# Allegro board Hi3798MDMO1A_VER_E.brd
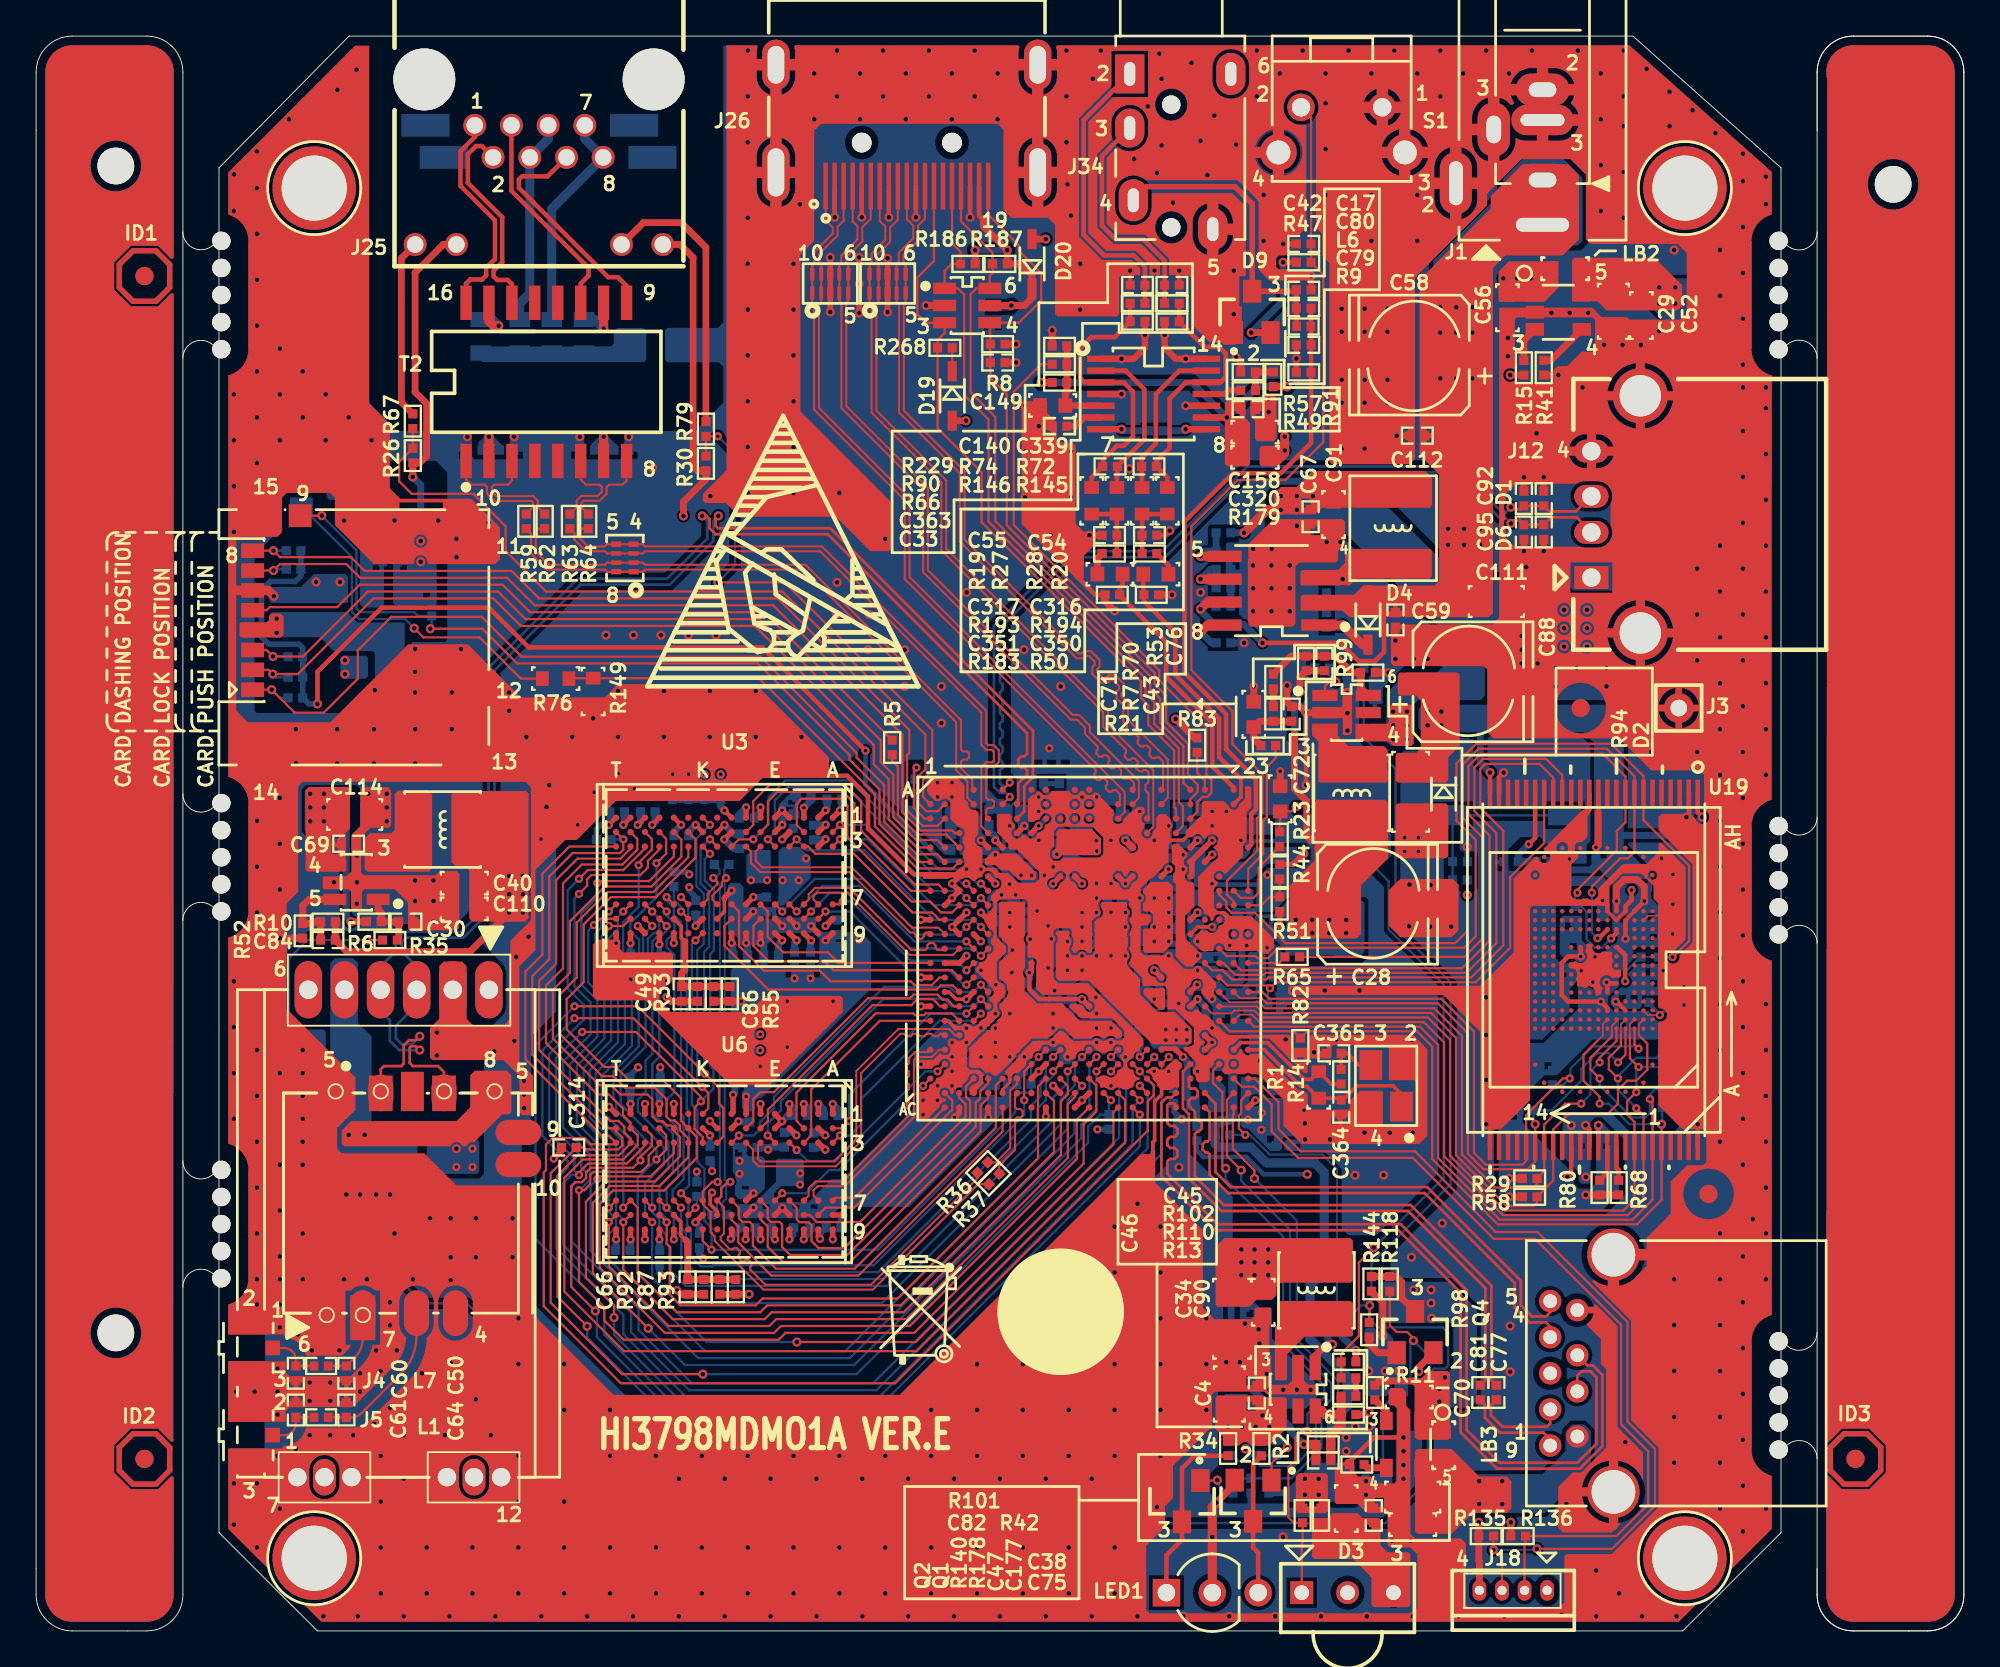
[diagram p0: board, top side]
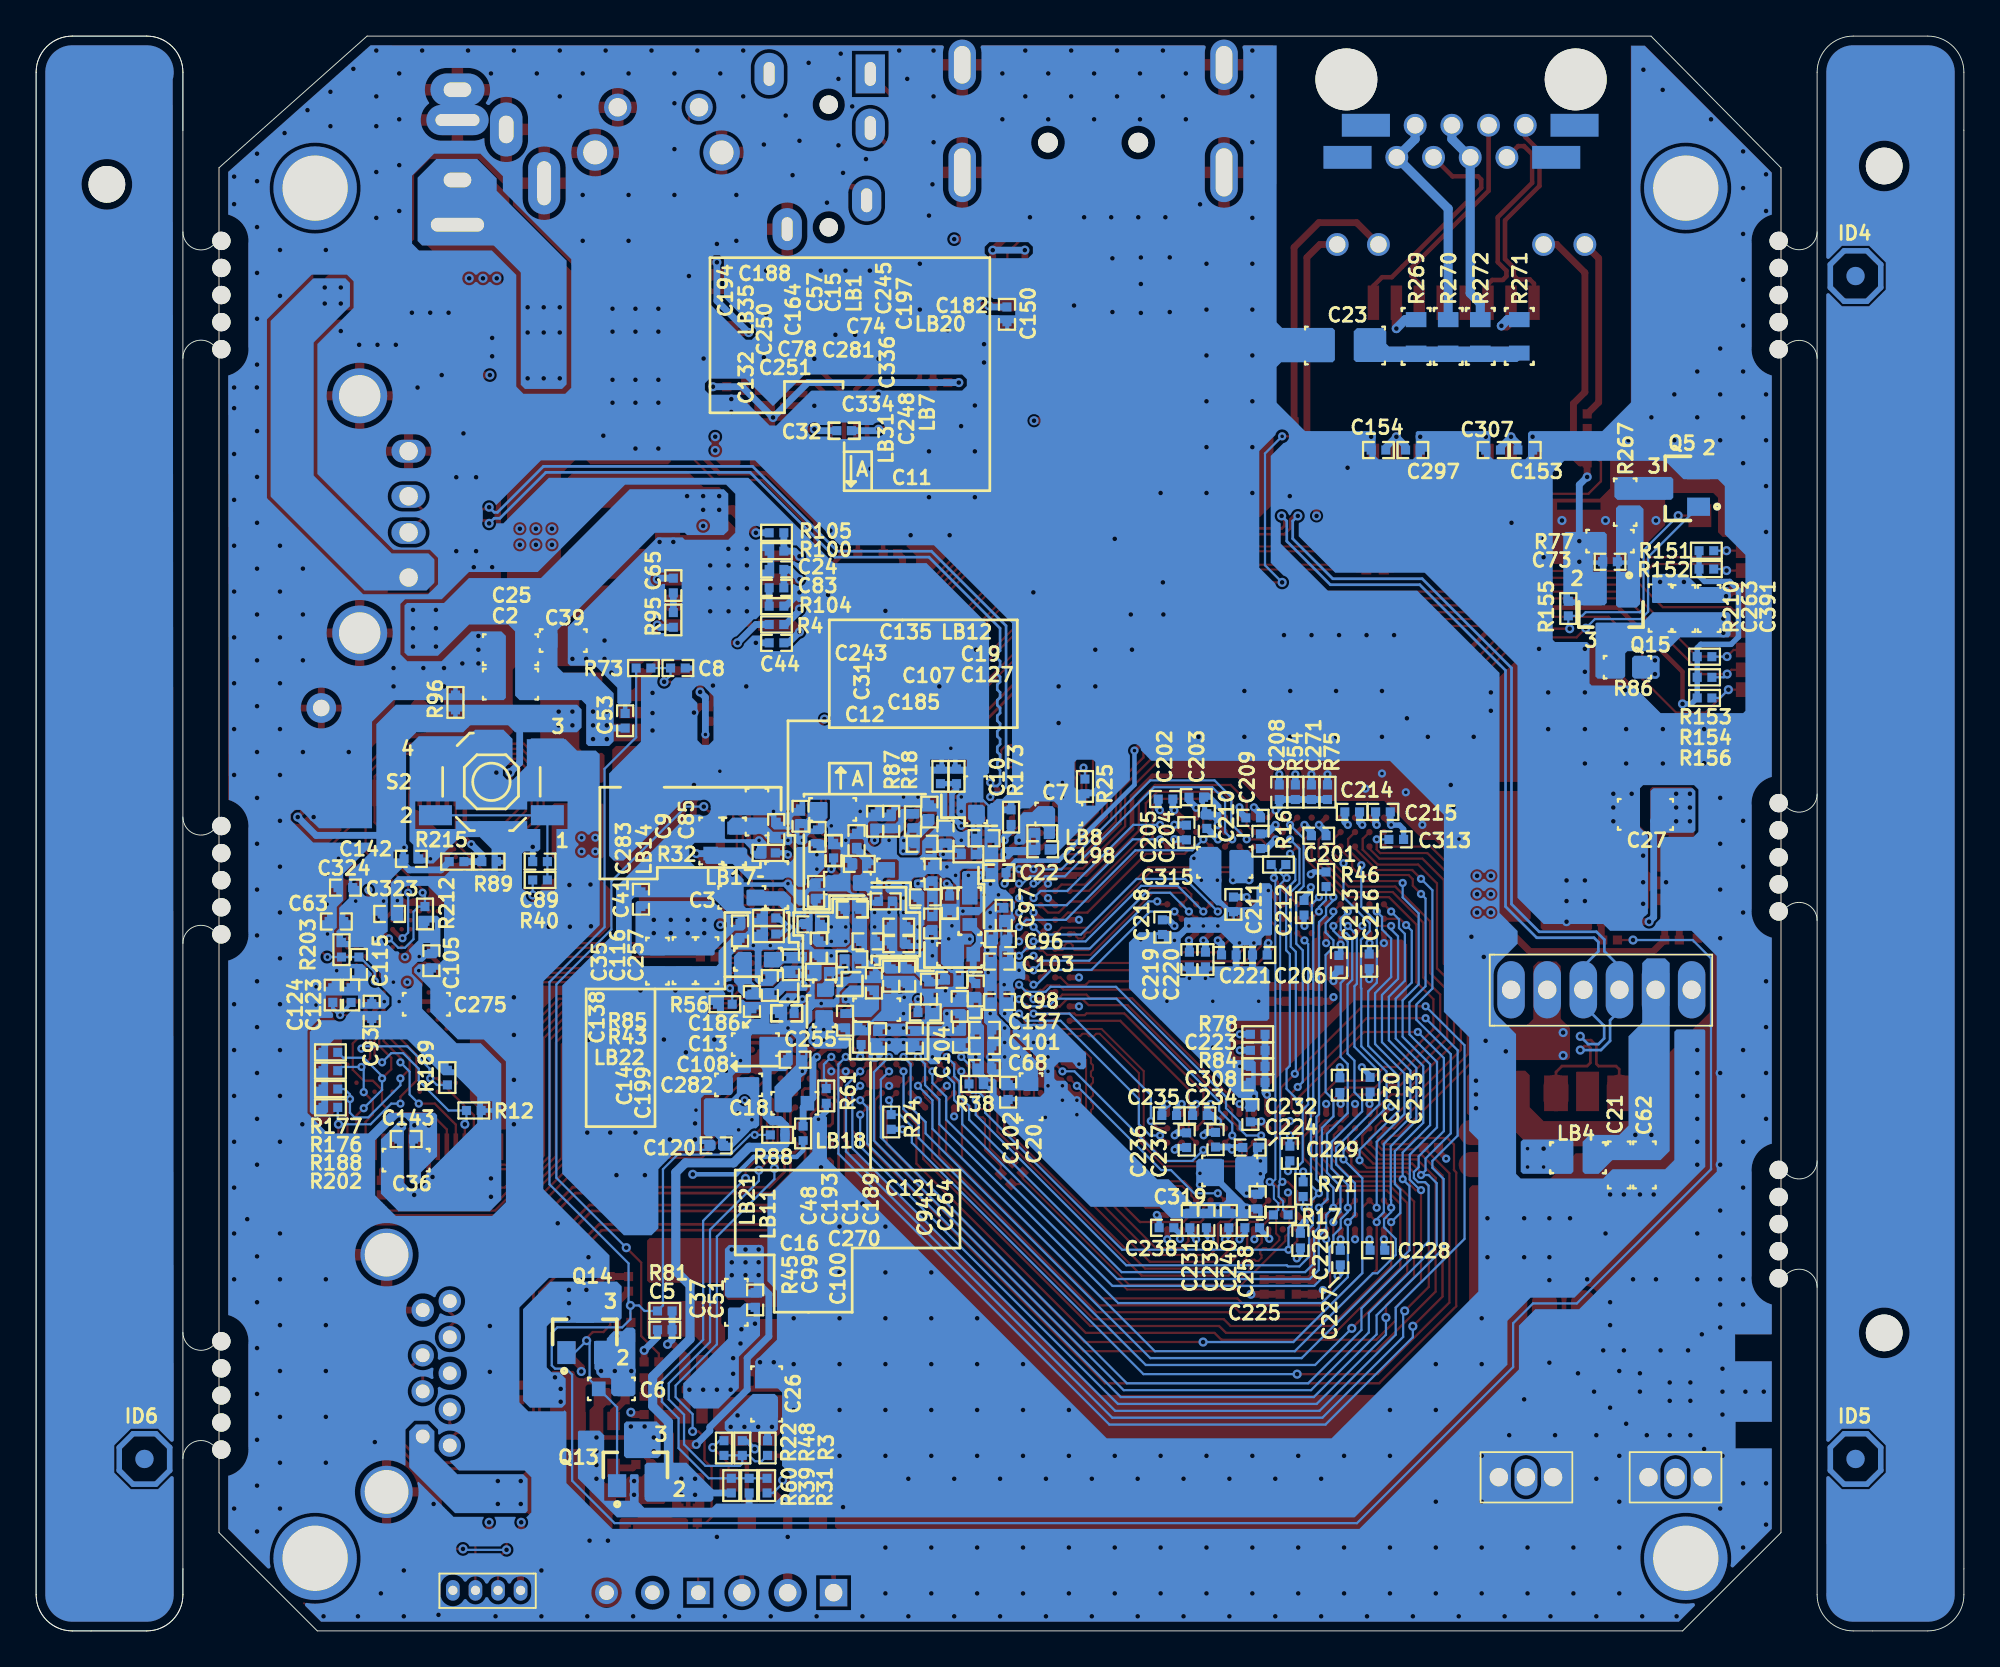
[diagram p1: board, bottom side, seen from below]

Outline 106.76 x 88.35 mm; copper layers: TOP, GND02, POWER03, BOTTOM. Coordinates in mm from the lower left corner of the outline.
Outline path: 98.63,86.35 98.63,83.14 ; 98.63,86.35 arc(99.21,87.76) 100.63,88.35 ; 98.63,86.35 arc(99.21,87.76) 100.63,88.35 ; 98.63,86.35 98.63,83.14 ; 98.63,83.14 98.63,3.43 ; 100.63,88.35 104.76,88.35 ; 100.63,88.35 104.76,88.35 ; 98.63,3.43 98.63,2 ; 98.63,3.43 98.63,2 ; 98.63,2 arc(99.21,0.59) 100.63,0 ; 98.63,2 arc(99.21,0.59) 100.63,0 ; 104.76,88.35 arc(106.17,87.76) 106.76,86.35 ; 104.76,88.35 arc(106.17,87.76) 106.76,86.35 ; 100.63,0 103.71,0 ; 100.63,0 103.71,0 ; 103.71,0 104.76,0 ; 103.71,0 104.76,0 ; 104.76,0 arc(106.17,0.59) 106.76,2 ; 104.76,0 arc(106.17,0.59) 106.76,2 ; 106.76,86.35 106.76,2 ; 106.76,86.35 106.76,2 ; 0,86.35 0,2 arc(0.59,0.59) 2,0 6.13,0 arc(7.54,0.59) 8.13,2 8.13,86.35 arc(7.54,87.76) 6.13,88.35 2,88.35 arc(0.59,87.76) 0,86.35 ; 10.13,81.05 17.33,88.35 88.43,88.35 96.63,81.05 96.63,5.44 91.18,0 15.57,0 10.13,5.45 10.13,81.05

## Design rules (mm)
constraint set DEFAULT: min track width 0.127
net group $5N541: nets 5V0 $5N541
net group $5N549: nets $5N549 STANDBY_PWROFF
net group $7N1630: nets $7N1630 USB_BOOT
net group $8N1514: nets $8N1514 DDR_CLK1P
net group $8N1515: nets $8N1515 DDR_CLK1N
net group $14N708: nets $14N708 USB3_TXN
net group $14N709: nets $14N709 USB3_TXP
net group $17N167: nets $17N167 TX+_PHY0
net group $17N169: nets $17N169 TX-_PHY0
net group DIFF: nets RX+_PHY0 RX-_PHY0
net group DIFFPAIR8: nets DDR_DQS0N DDR_DQS0P
net group DIFFPAIR9: nets DDR_DQS1N DDR_DQS1P
net group DIFFPAIR10: nets DDR_DQS2N DDR_DQS2P
net group DIFFPAIR11: nets DDR_DQS3N DDR_DQS3P
net group DIFFPAIR21: nets $17N178 $17N179
net group DIFFPAIR22: nets $17N175 $17N176
net group DIFFPAIR23: nets USB3_RXN USB3_RXP
net group USB: nets USB3_DM USB3_DP
net group 00: nets GND
net group 01: nets ADAC_VOUTL ADAC_VOUTR MUTE_CTRL
net group 02: nets 1V1_CPU
net group $17N168: nets $17N168
net group $17N182: nets $17N182
net group DDR: nets DDR_ADDR0 DDR_ADDR1 DDR_ADDR2 DDR_ADDR3 DDR_ADDR4 DDR_ADDR5 DDR_ADDR6 DDR_ADDR7 DDR_ADDR8 DDR_ADDR9 DDR_ADDR10 DDR_ADDR11 DDR_ADDR12 DDR_ADDR13 DDR_ADDR14 DDR_ADDR15 DDR_BA0 DDR_BA1 DDR_BA2 DDR_CASN DDR_CKE DDR_CSN DDR_DM0 DDR_DM1 DDR_DM2 DDR_DM3 DDR_DQ0 DDR_DQ1 DDR_DQ2 DDR_DQ3 DDR_DQ4 DDR_DQ5 DDR_DQ6 DDR_DQ7 DDR_DQ8 DDR_DQ9 DDR_DQ10 DDR_DQ11 DDR_DQ12 DDR_DQ13 DDR_DQ14 DDR_DQ15 DDR_DQ16 DDR_DQ17 DDR_DQ18 DDR_DQ19 DDR_DQ20 DDR_DQ21 DDR_DQ22 DDR_DQ23 DDR_DQ24 DDR_DQ25 DDR_DQ26 DDR_DQ27 DDR_DQ28 DDR_DQ29 DDR_DQ30 DDR_DQ31 DDR_ODT DDR_RASN DDR_RESETN DDR_WEN
net group DIFF90: nets USB0_DM USB0_DP USB1_DM USB1_DP
net group POWER: nets 1V1_CORE 1V5_DDR3 3V3_MOS
net group VIN: nets 3V3

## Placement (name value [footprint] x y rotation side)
C1  1NF  [SC0402]  58.52 36.27 270 bottom
C2  22UF  [SC0805]  80.49 52.45 0 bottom
C3  220NF  [SC0603]  67.67 40.64 0 bottom
C4  22UF  [SC0805]  66.07 13.13 90 top
C5  1NF  [SC0402]  71.94 16.68 0 bottom
C6  220NF  [SC0603]  74.9 13.41 0 bottom
C7  220NF  [SC0603]  50.12 45.26 180 bottom
C8  1NF  [SC0402]  71.21 53.34 180 bottom
C9  220NF  [SC0603]  66.84 45.36 90 bottom
C10  220NF  [SC0603]  54.72 46.05 90 bottom
C11  220NF  [SC0603]  55.56 37.49 0 bottom
C12  1NF  [SC0402]  63.28 36.51 0 bottom
C13  220NF  [SC0603]  66.92 32.48 0 bottom
C14  1NF  [SC0402]  66.12 35.76 90 bottom
C15  1NF  [SC0402]  59.41 44.85 90 bottom
C16  220NF  [SC0603]  60.21 34.41 180 bottom
C17  1NF  [SC0402]  70.2 74.3 0 top
C18  220NF  [SC0603]  64.74 29.23 0 bottom
C19  1NF  [SC0402]  58.99 39.01 180 bottom
C20  220NF  [SC0603]  51.66 29.59 270 bottom
C21  220NF  [SC0603]  19.09 25.81 270 bottom
C22  330N  [HSC0402]  53.45 42.01 180 bottom
C23  1NF  [SC1206]  34.27 71.21 0 bottom
C24  1NF  [SC0402]  65.75 58.8 0 bottom
C25  22UF  [SC0805]  80.49 54.36 0 bottom
C26  22UF  [SC0805]  66.3 13.13 90 bottom
C27  22UF  [SC0805]  17.64 45.23 0 bottom
C28  100UF  [SAC6666]  74.29 40.25 0 top
C29  22UF  [SC0805]  87.34 73.1 270 top
C30  1NF  [SC0402]  20.48 39.29 0 top
C31  330N  [HSC0402]  63.41 37.82 270 bottom
C32  330N  [HSC0402]  62.01 66.49 0 bottom
C33  330N  [HSC0402]  56.68 66.74 0 top
C34  1NF  [SC1206]  66.23 17.29 270 top
C35  220NF  [SC0603]  72.35 37.1 270 bottom
C36  220NF  [SC0603]  86.27 26.08 180 bottom
C37  220NF  [SC0603]  67.98 18.21 270 bottom
C38  22UF  [SC0805]  76.23 7.41 180 top
C39  220NF  [SC0603]  77.56 54.86 180 bottom
C40  220NF  [SC0603]  23.71 41.42 180 top
C41  1NF  [SC0402]  73.26 40.53 90 bottom
C42  1NF  [SC0402]  70.2 76.83 0 top
C43  1NF  [SC0402]  69.53 50.8 90 top
C44  1NF  [SC0402]  65.75 54.74 0 bottom
C45  1NF  [SC0402]  72.68 14.91 0 top
C46  1NF  [SC0402]  67.6 13.18 90 top
C47  220NF  [SC0603]  72.55 6.78 90 top
C48  1NF  [SC0402]  60.36 35.89 90 bottom
C49  1NF  [SC0402]  35.75 35.29 90 top
C50  1NF  [SC0402]  17.18 14.27 270 top
C51  1NF  [SC0402]  66.94 18.33 270 bottom
C52  220NF  [SC0603]  88.89 72.87 270 top
C53  1NF  [SC0402]  74.14 50.42 90 bottom
C54  1NF  [SC0402]  61.63 64.51 180 top
C55  1NF  [SC0402]  59.47 64.51 180 top
C56  220NF  [SC0603]  81.48 73.3 270 top
C57  1NF  [SC0402]  60.29 44.85 90 bottom
C58  100UF  [SAC6666]  76.05 70.68 180 top
C59  1NF  [SC0402]  75.28 56.01 270 top
C60  1NF  [SC0402]  14.39 14.27 270 top
C61  1NF  [SC0402]  14.39 12.24 90 top
C62  220NF  [SC0603]  17.69 25.81 270 bottom
C63  1NF  [SC0402]  90.13 39.3 0 bottom
C64  1NF  [SC0402]  17.18 12.24 90 top
C65  1NF  [SC0402]  71.47 57.91 90 bottom
C66  1NF  [SC0402]  36.08 19.06 90 top
C67  1NF  [SC0402]  70.58 61.72 270 top
C68  1NF  [SC0402]  54.24 31.19 0 bottom
C69  1NF  [SC0402]  17.31 43.61 0 top
C70  220NF  [SC0603]  76.04 12.95 180 top
C71  220NF  [SC0603]  67.43 50.77 90 top
C72  220NF  [SC0603]  68.89 46.1 90 top
C73  1NF  [SC0402]  19.6 59.23 180 bottom
C74  1NF  [SC0402]  57.69 43.61 180 bottom
C75  220NF  [SC0603]  76.23 5.89 180 top
C76  1NF  [SC0402]  71.34 53.59 270 top
C77  1NF  [SC0402]  80.87 13.21 90 top
C78  1NF  [SC0402]  61.17 42.49 0 bottom
C79  1NF  [SC0402]  70.2 71.25 180 top
C80  1NF  [SC0402]  70.2 73.28 180 top
C81  1NF  [SC0402]  79.98 13.21 90 top
C82  1NF  [SC0402]  71.28 9.44 180 top
C83  1NF  [SC0402]  65.75 57.78 0 bottom
C84  1NF  [SC0402]  16.16 38.27 0 top
C85  1NF  [SC0402]  65.77 44.39 90 bottom
C86  1NF  [SC0402]  37.53 35.29 270 top
C87  1NF  [SC0402]  37.86 19.06 270 top
C88  100UF  [SAC6666]  79.57 52.58 0 top
C89  1NF  [SC0402]  78.85 42.62 0 bottom
C90  220NF  [SC0603]  67.95 18.21 270 top
C91  220NF  [SC0603]  71.85 61.85 270 top
C92  1NF  [SC0402]  82.39 62.73 90 top
C93  1NF  [SC0402]  88.17 34.34 90 bottom
C94  1NF  [SC0402]  55.61 34.59 90 bottom
C95  1NF  [SC0402]  82.39 60.88 270 top
C96  1NF  [SC0402]  53.35 38.32 180 bottom
C97  1NF  [SC0402]  53.17 39.64 270 bottom
C98  1NF  [SC0402]  53.4 34.84 180 bottom
C99  1NF  [SC0402]  60.13 32.81 270 bottom
C100  1NF  [SC0402]  58.1 32.84 270 bottom
C101  1NF  [SC0402]  54.24 32.41 0 bottom
C102  1NF  [SC0402]  52.93 29.84 270 bottom
C103  1NF  [SC0402]  53.4 37.08 180 bottom
C104  1NF  [SC0402]  55.53 32.89 270 bottom
C105  1NF  [SC0402]  84.87 37.13 270 bottom
C107  1NF  [SC0402]  60.69 38.2 0 bottom
C108  1NF  [SC0402]  64.73 31.64 180 bottom
C110  220NF  [SC0603]  23.71 40 180 top
C111  22UF  [SC0805]  80.87 57.02 0 top
C112  1NF  [SC0402]  76.49 66.21 180 top
C114  22UF  [SC0805]  17.64 45.23 0 top
C115  1NF  [SC0402]  88.88 36.92 270 bottom
C116  220NF  [SC0603]  70.87 37.13 270 bottom
C120  1NF  [SC0402]  69.1 26.89 0 bottom
C121  1NF  [SC0402]  56.04 36.06 180 bottom
C123  1NF  [SC0402]  89.31 35.22 90 bottom
C124  1NF  [SC0402]  90.33 35.22 90 bottom
C127  1NF  [SC0402]  58.99 38.04 180 bottom
C132  1NF  [SC0402]  63.56 40.97 90 bottom
C135  330N  [HSC0402]  61.55 39.98 180 bottom
C137  1NF  [SC0402]  54.24 33.29 0 bottom
C138  1NF  [SC0402]  67.78 38.78 270 bottom
C140  1NF  [SC0402]  60.99 74.56 180 top
C142  1NF  [SC0402]  85.98 42.77 180 bottom
C143  1NF  [SC0402]  86.26 27.25 180 bottom
C149  1NF  [SC0402]  53.25 70.27 0 top
C150  1NF  [SC0402]  52.99 72.93 270 bottom
C153  1NF  [SC0402]  24.29 65.42 180 bottom
C154  1NF  [SC0402]  32.42 65.42 0 bottom
C158  1NF  [SC0402]  67.12 67.68 0 top
C164  1NF  [SC0402]  61.32 43.79 90 bottom
C177  1NF  [SC0402]  74.08 6.4 90 top
C182  1NF  [SC0402]  54.26 43.91 180 bottom
C185  1NF  [SC0402]  61.58 37.21 180 bottom
C186  1NF  [SC0402]  67.12 34.87 270 bottom
C188  220NF  [SC0603]  62.65 45.51 180 bottom
C189  1NF  [SC0402]  57.31 35.56 270 bottom
C193  1NF  [SC0402]  59.41 36.27 270 bottom
C194  1NF  [SC0402]  64.42 45.13 90 bottom
C197  1NF  [SC0402]  56.4 44.04 90 bottom
C198  1NF  [SC0402]  51.01 43.3 180 bottom
C199  1NF  [SC0402]  64.96 36.9 270 bottom
C201  1NF  [SC0402]  35.73 44.05 180 bottom
C202  1NF  [SC0402]  44.21 46.08 180 bottom
C203  1NF  [SC0402]  42.51 46.18 180 bottom
C204  1NF  [SC0402]  41.92 44.86 90 bottom
C205  1NF  [SC0402]  43.06 44.23 270 bottom
C206  1NF  [SC0402]  38.99 37.44 0 bottom
C208  1NF  [SC0402]  37.91 46.46 270 bottom
C209  1NF  [SC0402]  39.36 45.04 180 bottom
C210  1NF  [SC0402]  38.95 43.75 90 bottom
C211  1NF  [SC0402]  40.45 40.25 270 bottom
C212  1NF  [SC0402]  36.54 40.06 90 bottom
C213  1NF  [SC0402]  34.61 37.01 270 bottom
C214  1NF  [SC0402]  33.87 45.37 180 bottom
C215  1NF  [SC0402]  32.17 45.37 180 bottom
C216  1NF  [SC0402]  32.93 37.09 270 bottom
C218  1NF  [SC0402]  44.39 38.98 270 bottom
C219  1NF  [SC0402]  42.89 37.19 270 bottom
C220  1NF  [SC0402]  42 37.19 270 bottom
C221  1NF  [SC0402]  40.71 37.45 180 bottom
C223  1NF  [SC0402]  39.11 32.16 180 bottom
C224  1NF  [SC0402]  39.52 26.78 0 bottom
C225  1NF  [SC0402]  39.41 22.33 0 bottom
C226  1NF  [SC0402]  36.74 21.62 270 bottom
C227  1NF  [SC0402]  34.53 20.68 270 bottom
C228  1NF  [SC0402]  32.48 21.09 180 bottom
C229  1NF  [SC0402]  37.33 26.45 270 bottom
C230  1NF  [SC0402]  34.56 30.23 90 bottom
C231  1NF  [SC0402]  42.86 22.74 90 bottom
C232  1NF  [SC0402]  39.51 28.61 90 bottom
C233  1NF  [SC0402]  32.88 30.26 90 bottom
C234  1NF  [SC0402]  42.31 28.56 180 bottom
C235  1NF  [SC0402]  44.01 28.56 180 bottom
C236  1NF  [SC0402]  43.04 27.18 270 bottom
C237  1NF  [SC0402]  41.44 27.21 270 bottom
C238  1NF  [SC0402]  44.16 22.33 180 bottom
C239  1NF  [SC0402]  41.95 22.74 90 bottom
C240  1NF  [SC0402]  40.71 22.74 90 bottom
C243  1NF  [SC0402]  63.74 39.14 0 bottom
C245  1NF  [SC0402]  57.29 45.36 90 bottom
C248  330N  [HSC0402]  56.17 40.31 270 bottom
C250  330N  [HSC0402]  62.59 43.23 270 bottom
C251  220NF  [SC0603]  61.83 41.42 0 bottom
C255  330N  [HSC0402]  65.19 34.21 180 bottom
C257  220NF  [SC0603]  69.6 37.13 270 bottom
C258  1NF  [SC0402]  39.11 23.78 270 bottom
C263  220NF  [SC0603]  15.5 56.64 90 bottom
C264  1NF  [SC0402]  54.72 35.45 270 bottom
C270  1NF  [SC0402]  57.51 34.26 180 bottom
C271  1NF  [SC0402]  36.13 46.46 90 bottom
C275  220NF  [SC0603]  85.15 34.71 180 bottom
C281  220NF  [SC0603]  58.89 42.16 180 bottom
C282  220NF  [SC0603]  67.85 30.25 0 bottom
C283  220NF  [SC0603]  69.4 43.76 90 bottom
C297  1NF  [SC0402]  30.51 65.42 180 bottom
C307  1NF  [SC0402]  26.07 65.42 0 bottom
C308  1NF  [SC0402]  39.11 30.39 0 bottom
C313  1NF  [SC0402]  31.43 43.85 180 bottom
C314  1NF  [SC0402]  29.5 26.78 180 top
C315  22UF  [SC0805]  40.93 42.58 0 bottom
C316  1NF  [SC0402]  61.65 60.7 0 top
C317  1NF  [SC0402]  59.44 60.7 180 top
C319  22UF  [SC0805]  40.65 25.48 0 bottom
C320  220NF  [SC0603]  67.5 66.41 0 top
C323  1NF  [SC0402]  87.18 39.72 180 bottom
C324  1NF  [SC0402]  89.63 41.18 0 bottom
C334  1NF  [SC0402]  57.51 40.64 0 bottom
C336  1NF  [SC0402]  57.11 41.93 90 bottom
C339  1NF  [SC0402]  62.9 74.56 0 top
C350  220NF  [SC0603]  62.01 58.54 180 top
C351  220NF  [SC0603]  59.47 58.54 180 top
C363  220NF  [SC0603]  56.3 67.88 180 top
C364  1NF  [SC0402]  72.28 29 270 top
C365  1NF  [SC0402]  71.87 32 180 top
C391  220NF  [SC0603]  14.11 56.64 90 bottom
D1  1NF  [SC0402]  83.49 62.73 90 top
D2  D_A  [HSOD323A]  77.95 46.35 90 top
D3  IR  [SEN3-100C]  72.63 2.12 0 top
D4  D_A  [HSOD323A]  73.75 56.01 270 top
D6  1NF  [SC0402]  83.49 60.88 270 top
D9  D2-3_A  [SOT23]  67.34 73.07 0 top
D19  D_A  [HSOD323A]  50.73 68.41 90 top
D20  D_A  [HSOD323A]  55.15 75.73 270 top
ID1  PCB_MARKPOINT_A  [ID-BOARD]  6 75.06 0 top
ID2  PCB_MARKPOINT_A  [ID-BOARD]  6 9.53 0 top
ID3  PCB_MARKPOINT_A  [ID-BOARD]  100.76 9.53 0 top
ID4  PCB_MARKPOINT_A  [ID-BOARD]  6 75.06 180 bottom
ID5  PCB_MARKPOINT_A  [ID-BOARD]  6 9.53 180 bottom
ID6  PCB_MARKPOINT_A  [ID-BOARD]  100.76 9.53 180 bottom
J1  DC_012_HW  [PWC3-RF-A]  83.42 77.9 90 top
J2  VALUE  [SIP12-2_0MM-1827]  20.07 22.02 270 top
J3  NC  [SIP-1P]  90.97 51.13 0 top
J4  51_3612_50_H  [HSCOX-AMC-TM-A]  11.75 15.68 270 top
J5  51_3612_50_H  [HSCOX-AMC-TM-A]  11.75 10.84 270 top
J10  NC  [DC-002]  83.42 80.38 0 top
J12  SMDUSBA  [USB4-1415]  86.13 58.35 90 top
J13  USB3_ATYPE  [USB3_0_9P_DIP_MAINSUPER]  85.35 10.77 90 top
J18  SDW12501_4A_HW  [WBC0104-49T]  83.68 2.24 180 top
J21  5031820832  [MICRO_SD8-PUSH]  17.6 55.04 270 top
J25  406533_1  [MJ8-RLY]  24.29 83.41 0 top
J26  0  [WBC0119-20R-A]  48.22 85.19 180 top
J34  -  [VAF6-1107]  60.56 86.25 270 top
L1  1NH  [SL0402]  15.78 11.83 0 top
L2  3.3UH  [SWPA4020S]  72.86 46.43 270 top
L3  3.3UH  [SWPA4020S]  70.9 18.87 90 top
L4  3.3UH  [SWPA4020S]  22.51 44.39 0 top
L5  6.8UH  [SWPA5040S]  75.15 61.09 90 top
L6  1NH  [SL0402]  70.2 72.26 180 top
L7  1NH  [SL0402]  15.78 14.68 0 top
LB1  1NH  [SL0402]  58.2 44.85 270 bottom
LB2  MGLB1608_030T_LF  [SL0603]  84.68 75.46 180 top
LB3  MGLB1608_030T_LF  [SL0603]  77.95 10.29 90 top
LB4  MGLB2012_220T_LF  [SL0805]  21.37 26.21 0 bottom
LB7  MGLB1608_030T_LF  [SL0603]  55.05 39.87 90 bottom
LB8  1NH  [SL0402]  51.04 44.19 0 bottom
LB11  1NH  [SL0402]  61.96 33.8 90 bottom
LB12  1NH  [SL0402]  59.71 40.41 180 bottom
LB14  MGLB1608_030T_LF  [SL0603]  68.08 43.74 90 bottom
LB17  MGLB1608_030T_LF  [SL0603]  65.74 41.32 90 bottom
LB18  1NH  [SL0402]  64.28 27.56 90 bottom
LB20  1NH  [SL0402]  55.13 43.02 180 bottom
LB21  MGLB1608_030T_LF  [SL0603]  63.1 34.76 90 bottom
LB22  MGLB1608_030T_LF  [SL0603]  66.79 37.21 0 bottom
LB31  1NH  [SL0402]  57.13 39.19 90 bottom
LB35  1NH  [SL0402]  63.48 43.99 90 bottom
LED1  209_3SYGSURC_S530_A3HW  [LED3C-100C]  62.59 2.12 0 top
M20  M3_HOLE_A  [HOLE182-142]  91.3 4.02 0 top
M21  M3_HOLE_A  [HOLE182-142]  15.4 4.02 0 top
M22  M3_HOLE_A  [HOLE182-142]  91.3 79.93 0 top
M23  M3_HOLE_A  [HOLE182-142]  15.4 79.93 0 top
NOREF  -  []  -204.22 -199.15 0 top
NOREF#2  -  [unnamed#2]  97.63 41.59 90 top
NOREF#3  -  []  104.62 88.65 0 top
NOREF#4  -  []  -0.03 22.99 0 top
NOREF#5  -  []  138.77 142.52 180 top
NOREF#6  -  [unnamed#2]  9.13 42.86 270 top
NOREF#7  -  [unnamed#3]  4.41 81.15 0 top
NOREF#8  -  [unnamed#2]  97.63 74 90 top
NOREF#9  -  []  10.13 8.64 0 top
NOREF#10  -  []  51.53 17.91 0 top
NOREF#11  -  []  57.24 17.91 0 top
NOREF#12  -  []  41.88 56.77 0 top
NOREF#13  -  [unnamed#2]  9.13 74 270 top
NOREF#14  -  []  19.53 0 90 top
NOREF#15  -  [unnamed#2]  97.63 13.04 90 top
NOREF#16  -  []  55.55 188.89 0 top
NOREF#17  -  [unnamed#3]  4.41 16.51 0 top
NOREF#18  -  [unnamed#2]  9.13 22.54 270 top
NOREF#19  -  [unnamed#3]  102.84 80.14 0 top
NOREF#20  -  []  38.72 139.19 0 top
Q1  D2-3_A  [SOT23]  67.39 7.21 180 top
Q2  D2-3_A  [SOT23]  63.46 7.18 180 top
Q4  D2-3_A  [SOT23]  76.36 16.56 0 top
Q5  D2-3_A  [SOT23]  15.84 63.29 90 bottom
Q13  D2-3_A  [SOT23]  73.57 9.19 180 bottom
Q14  D2-3_A  [SOT23]  76.37 16.56 180 bottom
Q15  D2-3_A  [SOT23]  19.54 56.31 0 bottom
R1  5.1K  [SR0603]  71.03 30.25 270 top
R2  0/NC  [SR0402]  67.85 10.1 270 top
R3  0/NC  [SR0402]  66.25 10.13 270 bottom
R4  0/NC  [SR0402]  65.75 55.75 180 bottom
R5  0/NC  [SR0402]  47.41 48.94 270 top
R6  0/NC  [SR0402]  18.7 39.29 0 top
R7  0/NC  [SR0402]  68.51 50.8 270 top
R8  0/NC  [SR0402]  53.25 71.28 180 top
R9  0/NC  [SR0402]  70.2 69.72 180 top
R10  0/NC  [SR0402]  16.16 39.29 0 top
R11  0/NC  [SR0402]  74.14 13.21 90 top
R12  0/NC  [SR0402]  82.52 28.83 0 bottom
R13  0/NC  [SR0402]  72.68 11.98 180 top
R14  0/NC  [SR0402]  72.27 30.7 90 top
R15  0/NC  [SR0402]  82.39 69.98 270 top
R16  0/NC  [SR0402]  37.96 42.45 180 bottom
R17  0/NC  [SR0402]  37.83 23.05 180 bottom
R18  0/NC  [SR0402]  55.79 47.34 270 bottom
R19  5.1K  [SR0603]  58.45 62.6 90 top
R20  5.1K  [SR0603]  62.65 62.6 270 top
R21  0/NC  [SR0402]  68.23 49.04 0 top
R22  0/NC  [SR0402]  68.66 10.13 90 bottom
R23  0/NC  [SR0402]  68.87 43.86 270 top
R24  0/NC  [SR0402]  59.4 28.19 270 bottom
R25  0/NC  [SR0402]  48.68 46.78 90 bottom
R26  0/NC  [SR0402]  20.86 65.11 90 top
R27  5.1K  [SR0603]  59.85 62.6 90 top
R28  5.1K  [SR0603]  61.25 62.6 270 top
R29  0/NC  [SR0402]  82.71 25.07 0 top
R30  0/NC  [SR0402]  37.09 64.68 90 top
R31  0/NC  [SR0402]  66.28 8.05 270 bottom
R32  0/NC  [SR0402]  66.23 43.1 180 bottom
R33  0/NC  [SR0402]  36.64 35.29 90 top
R34  0/NC  [SR0402]  66.01 10.11 270 top
R35  0/NC  [SR0402]  19.59 38.27 0 top
R36  0/NC  [SR0402]  52.41 25.67 45 top
R37  0/NC  [SR0402]  53.05 25.04 45 top
R38  0/NC  [SR0402]  54.69 30.3 0 bottom
R39  0/NC  [SR0402]  67.27 8.05 270 bottom
R40  0/NC  [SR0402]  78.85 41.6 0 bottom
R41  0/NC  [SR0402]  83.49 69.98 90 top
R42  0/NC  [SR0402]  73.14 9.22 0 top
R43  0/NC  [SR0402]  66.2 38.6 0 bottom
R44  0/NC  [SR0402]  68.87 42.06 90 top
R45  0/NC  [SR0402]  61.07 32.89 90 bottom
R46  0/NC  [SR0402]  35.32 41.64 270 bottom
R47  0/NC  [SR0402]  70.2 75.82 0 top
R48  0/NC  [SR0402]  67.65 10.13 90 bottom
R49  0/NC  [SR0402]  67.12 68.72 0 top
R50  0/NC  [SR0402]  61.76 57.4 0 top
R51  0/NC  [SR0402]  68.87 40.26 270 top
R52  0/NC  [SR0402]  14.77 38.78 270 top
R53  0/NC  [SR0402]  70.33 53.59 270 top
R54  0/NC  [SR0402]  37.02 46.46 270 bottom
R55  0/NC  [SR0402]  38.42 35.29 270 top
R56  0/NC  [SR0402]  68.61 34.72 180 bottom
R57  0/NC  [SR0402]  67.12 69.74 180 top
R58  0/NC  [SR0402]  82.71 24.05 0 top
R59  0/NC  [SR0402]  27.15 61.47 90 top
R60  0/NC  [SR0402]  68.26 8.05 90 bottom
R61  0/NC  [SR0402]  63 29.64 90 bottom
R62  0/NC  [SR0402]  28.16 61.47 90 top
R63  0/NC  [SR0402]  29.56 61.47 90 top
R64  0/NC  [SR0402]  30.57 61.47 90 top
R65  0/NC  [SR0402]  69.56 37.34 180 top
R66  0/NC  [SR0402]  56.68 69.15 180 top
R67  0/NC  [SR0402]  20.86 67.02 270 top
R68  0/NC  [SR0402]  87.64 24.56 270 top
R70  0/NC  [SR0402]  68.51 52.6 270 top
R71  0/NC  [SR0402]  36.59 24.47 270 bottom
R72  560  [HSR0402]  62.9 73.55 180 top
R73  0/NC  [SR0402]  73.12 53.34 180 bottom
R74  560  [HSR0402]  60.99 73.55 180 top
R75  0/NC  [SR0402]  35.24 46.46 90 bottom
R76  5.1K  [SR0603]  28.77 52.76 180 top
R77  5.1K  [SR0603]  19.6 60.37 180 bottom
R78  0/NC  [SR0402]  39.11 33.05 180 bottom
R79  0/NC  [SR0402]  37.09 66.58 270 top
R80  0/NC  [SR0402]  86.58 24.56 90 top
R81  0/NC  [SR0402]  71.94 17.72 180 bottom
R82  0/NC  [SR0402]  70.01 32.43 270 top
R83  0/NC  [SR0402]  64.3 49.07 90 top
R84  0/NC  [SR0402]  39.11 31.27 0 bottom
R85  0/NC  [SR0402]  66.2 39.49 0 bottom
R86  5.1K  [SR0603]  18.63 53.39 0 bottom
R87  0/NC  [SR0402]  56.68 47.34 270 bottom
R88  0/NC  [SR0402]  65.69 27.48 180 bottom
R89  0/NC  [SR0402]  81.67 42.62 180 bottom
R90  0/NC  [SR0402]  56.68 70.17 0 top
R91  0/NC  [SR0402]  68.51 69.33 90 top
R92  0/NC  [SR0402]  36.97 19.06 90 top
R93  0/NC  [SR0402]  38.75 19.06 270 top
R94  -  [SR1206]  76.12 46.48 90 top
R95  0/NC  [SR0402]  71.47 56.01 90 bottom
R96  0/NC  [SR0402]  83.53 51.44 270 bottom
R98  0/NC  [SR0402]  73.82 16.68 270 top
R99  0/NC  [SR0402]  73.75 53.09 180 top
R100  0/NC  [SR0402]  65.75 59.82 0 bottom
R101  0/NC  [SR0402]  71.28 10.33 180 top
R102  0/NC  [SR0402]  72.68 14.02 180 top
R104  0/NC  [SR0402]  65.75 56.77 180 bottom
R105  0/NC  [SR0402]  65.75 60.83 0 bottom
R110  0/NC  [SR0402]  72.68 13 0 top
R118  0/NC  [SR0402]  74.96 19.22 90 top
R135  0/NC  [SR0402]  80.3 5.25 0 top
R136  0/NC  [SR0402]  82.08 5.25 0 top
R140  0/NC  [SR0402]  70.14 6.4 90 top
R144  0/NC  [SR0402]  73.95 19.22 90 top
R145  0/NC  [SR0402]  62.9 72.53 180 top
R146  0/NC  [SR0402]  60.99 72.53 0 top
R149  5.1K  [SR0603]  30.84 52.04 270 top
R151  0/NC  [SR0402]  14.26 59.84 180 bottom
R152  0/NC  [SR0402]  14.26 58.82 180 bottom
R153  0/NC  [SR0402]  14.36 53.97 180 bottom
R154  0/NC  [SR0402]  14.36 52.83 180 bottom
R155  0/NC  [SR0402]  21.91 56.64 270 bottom
R156  0/NC  [SR0402]  14.36 51.68 180 bottom
R173  0/NC  [SR0402]  52.76 45.08 90 bottom
R176  0/NC  [SR0402]  90.46 31.03 180 bottom
R177  0/NC  [SR0402]  90.46 32.05 180 bottom
R178  0/NC  [SR0402]  71.15 6.4 90 top
R179  5.1K  [SR0603]  67.5 65.01 180 top
R183  0/NC  [SR0402]  59.6 57.4 180 top
R186  0/NC  [SR0402]  51.6 75.73 0 top
R187  0/NC  [SR0402]  53.37 75.73 0 top
R188  0/NC  [SR0402]  90.46 30.02 180 bottom
R189  0/NC  [SR0402]  83.98 30.65 270 bottom
R193  0/NC  [SR0402]  59.44 59.68 0 top
R194  0/NC  [SR0402]  61.65 59.68 0 top
R202  0/NC  [SR0402]  90.46 29 180 bottom
R203  0/NC  [SR0402]  89.85 37.74 270 bottom
R210  5.1K  [SR0603]  16.83 56.66 90 bottom
R212  0/NC  [SR0402]  85.22 39.72 90 bottom
R215  0/NC  [SR0402]  83.47 42.62 180 bottom
R229  0/NC  [SR0402]  56.68 71.19 180 top
R267  5.1K  [SR0603]  18.76 62.53 90 bottom
R268  0/NC  [SR0402]  50.33 71.08 180 top
R269  75  [SR0805]  30.34 71.72 90 bottom
R270  75  [SR0805]  28.56 71.72 90 bottom
R271  75  [SR0805]  24.62 71.72 90 bottom
R272  75  [SR0805]  26.78 71.72 90 bottom
S1  MS-156  [TSW4-RG-C]  74.55 84.4 180 top
S2  TMG_533_T_R  [SPSW6-T]  81.54 47.04 0 bottom
T2  H1102T  [STFM16-50-285]  28.25 69.19 0 top
U1  VALUE  [TFBGA395-32-2323]  58.32 37.8 270 top
U2  CDT-CELKF04  [CDTWIFI]  20.59 23.69 90 top
U3  -  [BGA96-32-1609I]  38.12 41.85 180 top
U4  CS0806U  [SOT23A-6L]  51.56 73.42 270 top
U5  DIO2103_SGM8903  [SGM8903]  61.88 68.52 270 top
U6  -  [BGA96-32-1609I]  38.12 25.44 180 top
U7  NC  [CDTWIFI10]  20.21 23.71 90 top
U8  -  [RN8-0402]  32.61 59.44 90 top
U10  NC  [SOT23-5]  84.3 73.05 270 top
U11  EA8109_SY8032  [SOT23_6]  72.57 50.87 270 top
U12  NC  [SOT23-5]  75.73 10.33 180 top
U13  EA8109_SY8032  [SOT23_6]  69.88 13.38 180 top
U14  EA8253_ETA1486_MP1484  [SOIC8N]  68.41 57.63 90 top
U15  EA8108_SY8089A_ETA3409  [SOT23_5]  17.74 41.47 90 top
U19  NC  [SOP48-20-720B]  86.26 36.62 180 top
U22  EMMC  [BGA169-BGA153-0_5MM]  86.26 36.62 90 top
U23  CS0806S  [DFN2510P10E]  43.98 74.64 0 top
U24  CS0806S  [DFN2510P10E]  47.15 74.64 0 top
X2  24MHZ  [X288]  74.76 30.2 90 top

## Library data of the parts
C1 C5 C8 C12 C14 C15 C17 C19 C24 C30 C41-C46 C48-C51 C53-C55 C57 C59-C61 C63-C69 C73 C74 C76-C87 C89 C92-C105 C107 C108 C112 C115 C120 C121 C123 C124 C127 C132 C137 C138 C140 C142 C143 C149 C150 C153 C154 C158 C177 C182 C185 C186 C189 C193 C194 C197-C199 C201-C206 C208-C216 C218-C221 C223-C240 C243 C245 C258 C264 C270 C271 C297 C307 C308 C313 C314 C316 C317 C323 C324 C334 C336 C339 C364 C365 D1 D6 = SC0402
C2 C4 C25-C27 C29 C38 C111 C114 C315 C319 = SC0805
C3 C6 C7 C9-C11 C13 C16 C18 C20 C21 C35-C37 C39 C40 C47 C52 C56 C62 C70-C72 C75 C90 C91 C110 C116 C188 C251 C257 C263 C275 C281-C283 C320 C350 C351 C363 C391 = SC0603
C22 C31-C33 C135 C248 C250 C255 = HSC0402
C23 C34 = SC1206
C28 C58 C88 = SAC6666
C164 = SC0402: signal model: SC0402_10PF/NC
D2 D4 D19 D20 = HSOD323A
D3 = SEN3-100C
D9 Q1 Q2 Q4 Q5 Q13-Q15 = SOT23
ID1-ID6 = ID-BOARD
J1 = PWC3-RF-A
J2 = SIP12-2_0MM-1827
J3 = SIP-1P
J4 J5 = HSCOX-AMC-TM-A
J10 = DC-002
J12 = USB4-1415
J13 = USB3_0_9P_DIP_MAINSUPER
J18 = WBC0104-49T
J21 = MICRO_SD8-PUSH
J25 = MJ8-RLY
J26 = WBC0119-20R-A
J34 = VAF6-1107
L1 L6 L7 LB1 LB8 LB11 LB12 LB18 LB20 LB31 LB35 = SL0402
L2-L4 = SWPA4020S
L5 = SWPA5040S
LB2 LB3 LB7 LB14 LB17 LB21 LB22 = SL0603
LB4 = SL0805
LED1 = LED3C-100C
M20-M23 = HOLE182-142
R1 R19 R20 R27 R28 R76 R77 R86 R149 R179 R210 R267 = SR0603
R2-R18 R21-R26 R30-R35 R39-R44 R47-R53 R55-R57 R60 R61 R65-R68 R70 R71 R73 R75 R78-R85 R87-R93 R95 R96 R99-R102 R104 R105 R110 R118 R145 R146 R151-R156 R173 R176 R177 R183 R186-R189 R193 R194 R202 R203 R212 R229 R268 = SR0402
R29 R178 = SR0402: signal model: SR0402_75
R36-R38 R45 R46 = SR0402: signal model: SR0402_33
R54 = SR0402: signal model: SR0402_240
R58 R98 R135 R136 R140 = SR0402: signal model: SR0402_10K
R59 R62-R64 = SR0402: signal model: SR0402_0/NC
R72 R74 = HSR0402
R94 = SR1206
R144 R215 = SR0402: signal model: SR0402_4.7K
R269-R272 = SR0805
S1 = TSW4-RG-C
S2 = SPSW6-T
T2 = STFM16-50-285
U1 = TFBGA395-32-2323
U2 = CDTWIFI
U3 U6 = BGA96-32-1609I
U4 = SOT23A-6L
U5 = SGM8903
U7 = CDTWIFI10
U8 = RN8-0402
U10 U12 = SOT23-5
U11 U13 = SOT23_6
U14 = SOIC8N
U15 = SOT23_5
U19 = SOP48-20-720B
U22 = BGA169-BGA153-0_5MM
U23 U24 = DFN2510P10E
X2 = X288

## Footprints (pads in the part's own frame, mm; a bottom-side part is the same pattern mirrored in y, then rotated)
BGA96-32-1609I
  round 0.356 smd: A1(-6,-3.2) A2(-6,-2.4) A3(-6,-1.6) A7(-6,1.6) A8(-6,2.4) A9(-6,3.2) B1(-5.2,-3.2) B2(-5.2,-2.4) B3(-5.2,-1.6) B7(-5.2,1.6) B8(-5.2,2.4) B9(-5.2,3.2) C1(-4.4,-3.2) C2(-4.4,-2.4) C3(-4.4,-1.6) C7(-4.4,1.6) C8(-4.4,2.4) C9(-4.4,3.2) D1(-3.6,-3.2) D2(-3.6,-2.4) D3(-3.6,-1.6) D7(-3.6,1.6) D8(-3.6,2.4) D9(-3.6,3.2) E1(-2.8,-3.2) E2(-2.8,-2.4) E3(-2.8,-1.6) E7(-2.8,1.6) E8(-2.8,2.4) E9(-2.8,3.2) F1(-2,-3.2) F2(-2,-2.4) F3(-2,-1.6) F7(-2,1.6) F8(-2,2.4) F9(-2,3.2) G1(-1.2,-3.2) G2(-1.2,-2.4) G3(-1.2,-1.6) G7(-1.2,1.6) G8(-1.2,2.4) G9(-1.2,3.2) H1(-0.4,-3.2) H2(-0.4,-2.4) H3(-0.4,-1.6) H7(-0.4,1.6) H8(-0.4,2.4) H9(-0.4,3.2) J1(0.4,-3.2) J2(0.4,-2.4) J3(0.4,-1.6) J7(0.4,1.6) J8(0.4,2.4) J9(0.4,3.2) K1(1.2,-3.2) K2(1.2,-2.4) K3(1.2,-1.6) K7(1.2,1.6) K8(1.2,2.4) K9(1.2,3.2) L1(2,-3.2) L2(2,-2.4) L3(2,-1.6) L7(2,1.6) L8(2,2.4) L9(2,3.2) M1(2.8,-3.2) M2(2.8,-2.4) M3(2.8,-1.6) M7(2.8,1.6) M8(2.8,2.4) M9(2.8,3.2) N1(3.6,-3.2) N2(3.6,-2.4) N3(3.6,-1.6) N7(3.6,1.6) N8(3.6,2.4) N9(3.6,3.2) P1(4.4,-3.2) P2(4.4,-2.4) P3(4.4,-1.6) P7(4.4,1.6) P8(4.4,2.4) P9(4.4,3.2) R1(5.2,-3.2) R2(5.2,-2.4) R3(5.2,-1.6) R7(5.2,1.6) R8(5.2,2.4) R9(5.2,3.2) T1(6,-3.2) T2(6,-2.4) T3(6,-1.6) T7(6,1.6) T8(6,2.4) T9(6,3.2)
BGA169-BGA153-0_5MM
  round 1.016 smd: 1(-12.413,-6.351) 2(14.506,0.734)
  round 0.254 smd: A4(-6.75,-1.75) A6(-6.75,-0.75) A9(-6.75,0.75) A11(-6.75,1.75) AA2(3.25,-2.75) AA3(3.25,-2.25) AA4(3.25,-1.75) AA5(3.25,-1.25) AA6(3.25,-0.75) AA7(3.25,-0.25) AA8(3.25,0.25) AA9(3.25,0.75) AA10(3.25,1.25) AA11(3.25,1.75) AA12(3.25,2.25) AA13(3.25,2.75) AA14(3.25,3.25) AE1(5.25,-3.25) AE14(5.25,3.25) AG2(6.25,-2.75) AG13(6.25,2.75) AH4(6.75,-1.75) AH6(6.75,-0.75) AH9(6.75,0.75) AH11(6.75,1.75) B2(-6.25,-2.75) B13(-6.25,2.75) D1(-5.25,-3.25) D14(-5.25,3.25) H8(-3.25,0.25) H9(-3.25,0.75) H10(-3.25,1.25) H11(-3.25,1.75) H12(-3.25,2.25) H13(-3.25,2.75) H14(-3.25,3.25) J2(-2.75,-2.75) J3(-2.75,-2.25) J4(-2.75,-1.75) J5(-2.75,-1.25) J6(-2.75,-0.75) J7(-2.75,-0.25) J8(-2.75,0.25) J9(-2.75,0.75) J10(-2.75,1.25) J11(-2.75,1.75) J12(-2.75,2.25) J13(-2.75,2.75) J14(-2.75,3.25) K2(-2.25,-2.75) K3(-2.25,-2.25) K4(-2.25,-1.75) K5(-2.25,-1.25) K6(-2.25,-0.75) K7(-2.25,-0.25) K8(-2.25,0.25) K9(-2.25,0.75) K10(-2.25,1.25) K11(-2.25,1.75) K12(-2.25,2.25) K13(-2.25,2.75) K14(-2.25,3.25) L2(-1.75,-2.75) L3(-1.75,-2.25) L4(-1.75,-1.75) L12(-1.75,2.25) L13(-1.75,2.75) L14(-1.75,3.25) M1(-1.25,-3.25) M2(-1.25,-2.75) M3(-1.25,-2.25) M5(-1.25,-1.25) M6(-1.25,-0.75) M7(-1.25,-0.25) M8(-1.25,0.25) M9(-1.25,0.75) M10(-1.25,1.25) M12(-1.25,2.25) M13(-1.25,2.75) M14(-1.25,3.25) N1(-0.75,-3.25) N2(-0.75,-2.75) N3(-0.75,-2.25) N5(-0.75,-1.25) N10(-0.75,1.25) N12(-0.75,2.25) N13(-0.75,2.75) N14(-0.75,3.25) P1(-0.25,-3.25) P2(-0.25,-2.75) P3(-0.25,-2.25) P5(-0.25,-1.25) P10(-0.25,1.25) P12(-0.25,2.25) P13(-0.25,2.75) P14(-0.25,3.25) R1(0.25,-3.25) R2(0.25,-2.75) R3(0.25,-2.25) R5(0.25,-1.25) R10(0.25,1.25) R12(0.25,2.25) R13(0.25,2.75) R14(0.25,3.25) T1(0.75,-3.25) T2(0.75,-2.75) T3(0.75,-2.25) T5(0.75,-1.25) T10(0.75,1.25) T12(0.75,2.25) T13(0.75,2.75) T14(0.75,3.25) U1(1.25,-3.25) U2(1.25,-2.75) U3(1.25,-2.25) U5(1.25,-1.25) U6(1.25,-0.75) U7(1.25,-0.25) U8(1.25,0.25) U9(1.25,0.75) U10(1.25,1.25) U12(1.25,2.25) U13(1.25,2.75) U14(1.25,3.25) V1(1.75,-3.25) V2(1.75,-2.75) V3(1.75,-2.25) V12(1.75,2.25) V13(1.75,2.75) V14(1.75,3.25) W1(2.25,-3.25) W2(2.25,-2.75) W3(2.25,-2.25) W4(2.25,-1.75) W5(2.25,-1.25) W6(2.25,-0.75) W7(2.25,-0.25) W8(2.25,0.25) W9(2.25,0.75) W10(2.25,1.25) W11(2.25,1.75) W12(2.25,2.25) W13(2.25,2.75) W14(2.25,3.25) Y2(2.75,-2.75) Y3(2.75,-2.25) Y4(2.75,-1.75) Y5(2.75,-1.25) Y6(2.75,-0.75) Y7(2.75,-0.25) Y8(2.75,0.25) Y9(2.75,0.75) Y10(2.75,1.25) Y11(2.75,1.75) Y12(2.75,2.25) Y13(2.75,2.75) Y14(2.75,3.25)
  oval 0.203x0.254 smd: AA1(3.25,-3.25) H1(-3.25,-3.25) J1(-2.75,-3.25) K1(-2.25,-3.25) L1(-1.75,-3.25) Y1(2.75,-3.25)
  oval 0.254x0.203 smd: H2(-3.25,-2.75) H3(-3.25,-2.25) H4(-3.25,-1.75) H5(-3.25,-1.25) H6(-3.25,-0.75) H7(-3.25,-0.25)
CDTWIFI
  rect 1.981x1.524 smd: 1(6.087,4.005) 5(6.087,-4.795)
  rect 1.981x1.321 smd: 2(6.087,1.505) 4(6.087,-1.995)
  rect 2.184x1.27 smd: 3(6.189,-0.245)
  rect 2.489x1.397 smd: 6(-6.341,4.5) 7(-6.341,2.5)
CDTWIFI10
  oval 2.54x1.397 smd: 1(-6.1,4.121) 2(-6.1,2.121) 3(-6.1,-0.856) 4(-6.1,-3.015)
  oval 2.032x1.397 smd: 5(6.1,3.621) 6(6.1,1.121) 7(6.1,-2.379) 8(6.1,-5.179)
  oval 1.397x2.54 smd: 9(3.654,-6.5) 10(2.384,-6.5)
DC-002
  oval 2.997x1.803 hole 1.524x0.813: 1(0,0) 2(0,5)
  oval 1.803x2.997 hole 0.813x1.524: 3(-2.7,2.8)
DFN2510P10E
  oval 0.254x0.813 smd: 1(-1,-0.525) 5(1,-0.525) 6(1,0.525) 10(-1,0.525)
  oval 0.229x0.813 smd: 2(-0.5,-0.525) 4(0.5,-0.525) 7(0.5,0.525) 9(-0.5,0.525)
  oval 0.356x0.813 smd: 3(0,-0.525) 8(0,0.525)
HOLE182-142
  round 4.623 hole 3.607: 1(0,0)
HSC0402
  rect 0.508x0.508 smd: 1(-0.406,0) 2(0.406,0)
HSCOX-AMC-TM-A
  rect 0.813x0.813 smd: 1(0,1.35)
  rect 1.168x2.184 smd: 2(-1.326,0) 3(1.326,0)
HSOD323A
  rect 1.118x0.508 smd: 1(1.372,0) 2(-1.372,0)
HSR0402
  rect 0.508x0.508 smd: 1(-0.406,0) 2(0.406,0)
ID-BOARD
  round 1.016 smd: 1(0,0)
LED3C-100C
  rect 1.524x1.524 hole 0.965: 1(0,0)
  round 1.524 hole 0.965: 2(2.54,0) 3(5.08,0)
MICRO_SD8-PUSH
  rect 0.813x1.27 smd: 1(2.9,-5.605) 2(1.8,-5.605) 3(0.7,-5.605) 4(-0.4,-5.605) 5(-1.5,-5.605) 6(-2.6,-5.605) 7(-3.7,-5.605) 8(-4.8,-5.605)
  rect 1.27x1.27 smd: 9(-6.74,-2.975) 10(-6.74,6.025)
  rect 1.524x1.143 smd: 11(-4.94,7.15) 12(2.84,7.15)
  rect 1.524x2.286 smd: 13(6.97,6.355) 15(-6.97,-5.125)
  rect 1.524x2.54 smd: 14(6.97,-4.975)
MJ8-RLY
  round 3.429 hole 3.429 unplated: (-2.794,2.54) (9.906,2.54)
  round 1.27 hole 0.914: 1(0,0) 2(1.016,-1.778) 3(2.032,0) 4(3.048,-1.778) 5(4.064,0) 6(5.08,-1.778) 7(6.096,0) 8(7.112,-1.778) 9(-3.302,-6.604) 10(-1.016,-6.604) 11(8.128,-6.604) 12(10.414,-6.604)
PWC3-RF-A
  rect 1.778x3.962 hole 0.762x2.946: 1(0,0)
  oval 3.454x1.778 hole 2.438x0.762: 2(2.3,4.8)
  oval 1.676x3.454 hole 0.66x2.438: 3(5.8,0)
RN8-0402
  rect 0.305x0.559 smd: 1(-0.762,-0.483) 4(0.762,-0.483) 5(0.762,0.483) 8(-0.762,0.483)
  rect 0.254x0.559 smd: 2(-0.254,-0.483) 3(0.254,-0.483) 6(0.254,0.483) 7(-0.254,0.483)
SAC6666
  rect 3.175x1.016 smd: 1(-2.5,0) 2(2.5,0)
SC0402
  rect 0.508x0.508 smd: 1(-0.406,0) 2(0.406,0)
SC0603
  rect 0.762x0.813 smd: 1(-0.699,0) 2(0.699,0)
SC0805
  rect 0.991x1.27 smd: 1(-0.813,0) 2(0.813,0)
SC1206
  rect 1.295x1.651 smd: 1(-1.346,0) 2(1.346,0)
SEN3-100C
  rect 1.27x1.27 hole 0.813: 1(-2.54,0)
  round 1.27 hole 0.813: 2(0,0) 3(2.54,0)
SGM8903
  rect 0.356x1.524 smd: 1(-1.95,-2.921) 2(-1.3,-2.921) 3(-0.65,-2.921) 4(0,-2.921) 5(0.65,-2.921) 6(1.3,-2.921) 7(1.95,-2.921) 8(1.95,2.921) 9(1.3,2.921) 10(0.65,2.921) 11(0,2.921) 12(-0.65,2.921) 13(-1.3,2.921) 14(-1.95,2.921)
SIP12-2_0MM-1827
  oval 3.175x1.524 hole 1.016: 1(-13.5,5.005) 2(-13.5,3.005) 3(-13.5,1.005) 4(-13.5,-0.995) 5(-13.5,-2.995) 6(-13.5,-4.995)
  oval 2.032x1.27 hole 1.016: 7(13.5,-5.604) 8(13.5,-4.104) 9(13.5,-2.604) 10(13.5,2.681) 11(13.5,4.181) 12(13.5,5.681)
SIP-1P
  round 1.651 hole 0.914: 1(0,0)
SL0402
  rect 0.483x0.508 smd: 1(-0.394,0) 2(0.394,0)
SL0603
  rect 0.711x0.813 smd: 1(-0.74,0) 2(0.74,0)
SL0805
  rect 0.94x1.27 smd: 1(-0.851,0) 2(0.851,0)
SOIC8N
  rect 0.635x1.905 smd: 1(-1.905,-2.6) 2(-0.635,-2.6) 3(0.635,-2.6) 4(1.905,-2.6) 5(1.905,2.6) 6(0.635,2.6) 7(-0.635,2.6) 8(-1.905,2.6)
  rect 3.505x2.616 smd: 9(0,0)
SOP48-20-720B
  rect 0.254x1.473 smd: 1(-5.75,-9.802) 2(-5.25,-9.802) 3(-4.75,-9.802) 4(-4.25,-9.802) 5(-3.75,-9.802) 6(-3.25,-9.802) 7(-2.75,-9.802) 8(-2.25,-9.802) 9(-1.75,-9.802) 10(-1.25,-9.802) 11(-0.75,-9.802) 12(-0.25,-9.802) 13(0.25,-9.802) 14(0.75,-9.802) 15(1.25,-9.802) 16(1.75,-9.802) 17(2.25,-9.802) 18(2.75,-9.802) 19(3.25,-9.802) 20(3.75,-9.802) 21(4.25,-9.802) 22(4.75,-9.802) 23(5.25,-9.802) 24(5.75,-9.802) 25(5.75,9.802) 26(5.25,9.802) 27(4.75,9.802) 28(4.25,9.802) 29(3.75,9.802) 30(3.25,9.802) 31(2.75,9.802) 32(2.25,9.802) 33(1.75,9.802) 34(1.25,9.802) 35(0.75,9.802) 36(0.25,9.802) 37(-0.25,9.802) 38(-0.75,9.802) 39(-1.25,9.802) 40(-1.75,9.802) 41(-2.25,9.802) 42(-2.75,9.802) 43(-3.25,9.802) 44(-3.75,9.802) 45(-4.25,9.802) 46(-4.75,9.802) 47(-5.25,9.802) 48(-5.75,9.802)
SOT23
  rect 1.016x1.27 smd: 1(-1.016,-1.143) 2(1.016,-1.143) 3(0,1.143)
SOT23-5
  rect 0.711x1.016 smd: 1(-0.95,-1.3) 2(0,-1.3) 3(0.95,-1.3) 4(0.95,1.3) 5(-0.95,1.3)
SOT23_5
  rect 0.635x1.27 smd: 1(-0.95,-1.2) 2(0,-1.2) 3(0.95,-1.2) 4(0.95,1.2) 5(-0.95,1.2)
SOT23_6
  rect 0.635x1.397 smd: 1(-0.95,-1.2) 2(0,-1.2) 3(0.95,-1.2) 4(0.95,1.2) 5(0,1.2) 6(-0.95,1.2)
SOT23A-6L
  rect 0.635x1.27 smd: 1(-0.95,-1.25) 2(0,-1.25) 3(0.95,-1.25) 4(0.95,1.25) 5(0,1.25) 6(-0.95,1.25)
SPSW6-T
  rect 1.829x1.118 smd: 1(-3.1,1.85) 2(3.1,1.85) 3(-3.1,-1.85) 4(3.1,-1.85)
  rect 1.397x0.61 smd: 5(0,2.5) 6(0,-2.5)
SR0402
  rect 0.508x0.508 smd: 1(-0.406,0) 2(0.406,0)
SR0603
  rect 0.711x0.813 smd: 1(-0.737,0) 2(0.737,0)
SR0805
  rect 0.838x1.143 smd: 1(-0.927,0) 2(0.927,0)
SR1206
  rect 1.295x1.6 smd: 1(-1.346,0) 2(1.346,0)
STFM16-50-285
  rect 0.635x1.905 smd: 1(-4.445,-4.381) 2(-3.175,-4.381) 3(-1.905,-4.381) 4(-0.635,-4.381) 5(0.635,-4.381) 6(1.905,-4.381) 7(3.175,-4.381) 8(4.445,-4.381) 9(4.445,4.381) 10(3.175,4.381) 11(1.905,4.381) 12(0.635,4.381) 13(-0.635,4.381) 14(-1.905,4.381) 15(-3.175,4.381) 16(-4.445,4.381)
SWPA4020S
  rect 1.905x3.683 smd: 1(-1.55,0) 2(1.55,0)
SWPA5040S
  rect 1.397x4.191 smd: 1(-1.85,0) 2(1.85,0)
TFBGA395-32-2323
  round 0.356 smd: A1(-8.8,-8.8) A2(-8.8,-8) A3(-8.8,-7.2) A4(-8.8,-6.4) A6(-8.8,-4.8) A8(-8.8,-3.2) A9(-8.8,-2.4) A11(-8.8,-0.8) A12(-8.8,0) A15(-8.8,2.4) A17(-8.8,4) A19(-8.8,5.6) A20(-8.8,6.4) A22(-8.8,8) A23(-8.8,8.8) AA1(7.2,-8.8) AA2(7.2,-8) AA3(7.2,-7.2) AA4(7.2,-6.4) AA5(7.2,-5.6) AA6(7.2,-4.8) AA7(7.2,-4) AA8(7.2,-3.2) AA9(7.2,-2.4) AA10(7.2,-1.6) AA11(7.2,-0.8) AA12(7.2,0) AA13(7.2,0.8) AA14(7.2,1.6) AA15(7.2,2.4) AA16(7.2,3.2) AA17(7.2,4) AA18(7.2,4.8) AA19(7.2,5.6) AA20(7.2,6.4) AA21(7.2,7.2) AA22(7.2,8) AA23(7.2,8.8) AB1(8,-8.8) AB2(8,-8) AB3(8,-7.2) AB4(8,-6.4) AB5(8,-5.6) AB6(8,-4.8) AB7(8,-4) AB8(8,-3.2) AB9(8,-2.4) AB10(8,-1.6) AB11(8,-0.8) AB12(8,0) AB13(8,0.8) AB14(8,1.6) AB15(8,2.4) AB16(8,3.2) AB18(8,4.8) AB20(8,6.4) AB22(8,8) AB23(8,8.8) AC1(8.8,-8.8) AC2(8.8,-8) AC3(8.8,-7.2) AC5(8.8,-5.6) AC6(8.8,-4.8) AC8(8.8,-3.2) AC9(8.8,-2.4) AC11(8.8,-0.8) AC12(8.8,0) AC14(8.8,1.6) AC15(8.8,2.4) AC18(8.8,4.8) AC20(8.8,6.4) AC22(8.8,8) AC23(8.8,8.8) B1(-8,-8.8) B2(-8,-8) B3(-8,-7.2) B4(-8,-6.4) B6(-8,-4.8) B7(-8,-4) B8(-8,-3.2) B9(-8,-2.4) B11(-8,-0.8) B12(-8,0) B14(-8,1.6) B15(-8,2.4) B17(-8,4) B19(-8,5.6) B20(-8,6.4) B22(-8,8) B23(-8,8.8) C1(-7.2,-8.8) C2(-7.2,-8) C3(-7.2,-7.2) C4(-7.2,-6.4) C5(-7.2,-5.6) C6(-7.2,-4.8) C7(-7.2,-4) C8(-7.2,-3.2) C9(-7.2,-2.4) C10(-7.2,-1.6) C11(-7.2,-0.8) C12(-7.2,0) C13(-7.2,0.8) C14(-7.2,1.6) C15(-7.2,2.4) C16(-7.2,3.2) C17(-7.2,4) C18(-7.2,4.8) C19(-7.2,5.6) C20(-7.2,6.4) C21(-7.2,7.2) C22(-7.2,8) D3(-6.4,-7.2) D4(-6.4,-6.4) D5(-6.4,-5.6) D6(-6.4,-4.8) D7(-6.4,-4) D8(-6.4,-3.2) D9(-6.4,-2.4) D10(-6.4,-1.6) D11(-6.4,-0.8) D12(-6.4,0) D13(-6.4,0.8) D14(-6.4,1.6) D15(-6.4,2.4) D16(-6.4,3.2) D17(-6.4,4) D18(-6.4,4.8) D19(-6.4,5.6) D20(-6.4,6.4) D21(-6.4,7.2) D22(-6.4,8) E1(-5.6,-8.8) E2(-5.6,-8) E3(-5.6,-7.2) E4(-5.6,-6.4) E5(-5.6,-5.6) E6(-5.6,-4.8) E15(-5.6,2.4) E16(-5.6,3.2) E17(-5.6,4) E18(-5.6,4.8) E19(-5.6,5.6) E20(-5.6,6.4) E21(-5.6,7.2) E22(-5.6,8) E23(-5.6,8.8) F1(-4.8,-8.8) F2(-4.8,-8) F3(-4.8,-7.2) F4(-4.8,-6.4) F5(-4.8,-5.6) F19(-4.8,5.6) F20(-4.8,6.4) F21(-4.8,7.2) G3(-4,-7.2) G4(-4,-6.4) G5(-4,-5.6) G10(-4,-1.6) G11(-4,-0.8) G12(-4,0) G13(-4,0.8) G14(-4,1.6) G15(-4,2.4) G16(-4,3.2) G17(-4,4) G19(-4,5.6) G20(-4,6.4) G21(-4,7.2) H1(-3.2,-8.8) H2(-3.2,-8) H3(-3.2,-7.2) H4(-3.2,-6.4) H5(-3.2,-5.6) H10(-3.2,-1.6) H11(-3.2,-0.8) H12(-3.2,0) H13(-3.2,0.8) H14(-3.2,1.6) H15(-3.2,2.4) H16(-3.2,3.2) H17(-3.2,4) H19(-3.2,5.6) H20(-3.2,6.4) H21(-3.2,7.2) H22(-3.2,8) H23(-3.2,8.8) J2(-2.4,-8) J3(-2.4,-7.2) J4(-2.4,-6.4) J5(-2.4,-5.6) J6(-2.4,-4.8) J7(-2.4,-4) J10(-2.4,-1.6) J11(-2.4,-0.8) J12(-2.4,0) J13(-2.4,0.8) J14(-2.4,1.6) J15(-2.4,2.4) J16(-2.4,3.2) J17(-2.4,4) J19(-2.4,5.6) J20(-2.4,6.4) J21(-2.4,7.2) J22(-2.4,8) J23(-2.4,8.8) K1(-1.6,-8.8) K2(-1.6,-8) K3(-1.6,-7.2) K4(-1.6,-6.4) K5(-1.6,-5.6) K6(-1.6,-4.8) K7(-1.6,-4) K10(-1.6,-1.6) K11(-1.6,-0.8) K12(-1.6,0) K13(-1.6,0.8) K14(-1.6,1.6) K15(-1.6,2.4) K16(-1.6,3.2) K17(-1.6,4) K19(-1.6,5.6) K20(-1.6,6.4) K21(-1.6,7.2) L1(-0.8,-8.8) L2(-0.8,-8) L3(-0.8,-7.2) L4(-0.8,-6.4) L5(-0.8,-5.6) L6(-0.8,-4.8) L10(-0.8,-1.6) L11(-0.8,-0.8) L12(-0.8,0) L13(-0.8,0.8) L14(-0.8,1.6) L15(-0.8,2.4) L16(-0.8,3.2) L17(-0.8,4) L19(-0.8,5.6) L20(-0.8,6.4) L21(-0.8,7.2) L22(-0.8,8) L23(-0.8,8.8) M2(0,-8) M3(0,-7.2) M4(0,-6.4) M5(0,-5.6) M6(0,-4.8) M8(0,-3.2) M10(0,-1.6) M11(0,-0.8) M12(0,0) M13(0,0.8) M14(0,1.6) M15(0,2.4) M16(0,3.2) M17(0,4) M19(0,5.6) M20(0,6.4) M21(0,7.2) N1(0.8,-8.8) N2(0.8,-8) N3(0.8,-7.2) N4(0.8,-6.4) N5(0.8,-5.6) N6(0.8,-4.8) N8(0.8,-3.2) N10(0.8,-1.6) N11(0.8,-0.8) N12(0.8,0) N13(0.8,0.8) N14(0.8,1.6) N15(0.8,2.4) N16(0.8,3.2) N17(0.8,4) N19(0.8,5.6) N20(0.8,6.4) N21(0.8,7.2) N22(0.8,8) N23(0.8,8.8) P1(1.6,-8.8) P2(1.6,-8) P3(1.6,-7.2) P4(1.6,-6.4) P5(1.6,-5.6) P6(1.6,-4.8) P10(1.6,-1.6) P11(1.6,-0.8) P12(1.6,0) P13(1.6,0.8) P14(1.6,1.6) P15(1.6,2.4) P16(1.6,3.2) P17(1.6,4) P19(1.6,5.6) P20(1.6,6.4) P21(1.6,7.2) R2(2.4,-8) R3(2.4,-7.2) R4(2.4,-6.4) R5(2.4,-5.6) R6(2.4,-4.8) R16(2.4,3.2) R17(2.4,4) R19(2.4,5.6) R20(2.4,6.4) R21(2.4,7.2) R22(2.4,8) R23(2.4,8.8) T1(3.2,-8.8) T2(3.2,-8) T3(3.2,-7.2) T4(3.2,-6.4) T5(3.2,-5.6) T6(3.2,-4.8) T9(3.2,-2.4) T10(3.2,-1.6) T11(3.2,-0.8) T12(3.2,0) T17(3.2,4) T19(3.2,5.6) T20(3.2,6.4) T21(3.2,7.2) U1(4,-8.8) U2(4,-8) U3(4,-7.2) U4(4,-6.4) U5(4,-5.6) U6(4,-4.8) U7(4,-4) U20(4,6.4) U21(4,7.2) U22(4,8) U23(4,8.8) V2(4.8,-8) V3(4.8,-7.2) V4(4.8,-6.4) V5(4.8,-5.6) V6(4.8,-4.8) V7(4.8,-4) V8(4.8,-3.2) V9(4.8,-2.4) V10(4.8,-1.6) V11(4.8,-0.8) V12(4.8,0) V13(4.8,0.8) V14(4.8,1.6) V20(4.8,6.4) V21(4.8,7.2) W1(5.6,-8.8) W2(5.6,-8) W3(5.6,-7.2) W4(5.6,-6.4) W5(5.6,-5.6) W6(5.6,-4.8) W7(5.6,-4) W8(5.6,-3.2) W9(5.6,-2.4) W10(5.6,-1.6) W11(5.6,-0.8) W12(5.6,0) W13(5.6,0.8) W14(5.6,1.6) W15(5.6,2.4) W16(5.6,3.2) W17(5.6,4) W18(5.6,4.8) W19(5.6,5.6) W20(5.6,6.4) W21(5.6,7.2) W22(5.6,8) W23(5.6,8.8) Y1(6.4,-8.8) Y2(6.4,-8) Y3(6.4,-7.2) Y4(6.4,-6.4) Y5(6.4,-5.6) Y6(6.4,-4.8) Y7(6.4,-4) Y8(6.4,-3.2) Y9(6.4,-2.4) Y10(6.4,-1.6) Y11(6.4,-0.8) Y12(6.4,0) Y13(6.4,0.8) Y14(6.4,1.6) Y15(6.4,2.4) Y16(6.4,3.2) Y17(6.4,4) Y18(6.4,4.8) Y19(6.4,5.6) Y20(6.4,6.4) Y21(6.4,7.2) Y22(6.4,8) Y23(6.4,8.8)
TSW4-RG-C
  round 1.524 hole 1.016: 1(0,0) 2(4.5,0)
  round 2.032 hole 1.321: 3(-1.25,2.5) 4(5.75,2.5)
unnamed#2
  round 1.016 hole 1.016 unplated: (-3,1.13) (-1.5,1.13) (0,1.13) (1.5,1.13) (3,1.13)
unnamed#3
  round 2.032 hole 2.032 unplated: (0,0)
USB3_0_9P_DIP_MAINSUPER
  round 1.245 hole 0.762: 1(0,0) 2(2.5,0) 3(4.5,0) 4(7,0) 5(7.5,1.5) 6(5.5,1.5) 7(3.5,1.5) 8(1.5,1.5) 9(-0.5,1.5)
  round 2.896 hole 2.413: 10(-3.07,-2) 11(10.07,-2)
USB4-1415
  rect 1.27x1.905 hole 1.016: 1(0,0)
  oval 1.27x1.905 hole 1.016: 2(2.5,0) 3(4.5,0) 4(7,0)
  round 3.048 hole 2.286: 5(-3.07,-2.71) 6(10.07,-2.71)
VAF6-1107
  round 1.016 hole 1.016 unplated: (1.7,2.3) (8.5,2.3)
  rect 2.159x1.626 hole 1.321x0.61: 2(0,0)
  oval 2.159x1.626 hole 1.321x0.61: 3(3,0)
  oval 2.337x1.626 hole 1.321x0.61: 4(7,0.2) 5(8.6,4.6) 6(0,5.6)
WBC0104-49T
  oval 0.762x1.143 hole 0.508: 1(0,0) 2(1.25,0) 3(2.5,0) 4(3.75,0)
WBC0119-20R-A
  round 1.092 hole 1.092 unplated: (-2.5,2.745) (2.5,2.745)
  rect 0.254x2.591 smd: 1(4.5,5.155) 2(4,5.155) 3(3.5,5.155) 4(3,5.155) 5(2.5,5.155) 6(2,5.155) 7(1.5,5.155) 8(1,5.155) 9(0.5,5.155) 10(0,5.155) 11(-0.5,5.155) 12(-1,5.155) 13(-1.5,5.155) 14(-2,5.155) 15(-2.5,5.155) 16(-3,5.155) 17(-3.5,5.155) 18(-4,5.155) 19(-4.5,5.155)
  oval 1.524x3.302 hole 0.914x2.667: 20(-7.25,4.395) 21(7.25,4.395)
  oval 1.524x2.794 hole 0.914x2.083: 22(-7.25,-1.565) 23(7.25,-1.565)
X288
  rect 1.651x1.27 smd: 1(-1.15,-0.85) 2(1.15,-0.85) 3(1.15,0.85) 4(-1.15,0.85)

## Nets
1V1_CORE: C1.1 C19.1 C34.1 C37.1 C51.1 C82.2 C90.1 C107.1 C120.1 C121.1 C127.1 C189.1 C193.1 C282.1 L3.2 LB11.1 LB12.2 LB21.1 LB31.1 R101.2 U1.J13 U1.J14 U1.K13 U1.K14 U1.L10 U1.L13 U1.L14 U1.M10 U1.M13 U1.M14 U1.N10 U1.N11 U1.N12 U1.N13 U1.N14 U1.P10 U1.P11 U1.P12 U1.P13 U1.P14 U1.P15
1V1_CPU: C28.1 C31.1 C35.1 C41.1 C76.2 C116.1 C132.1 C135.1 C138.1 C243.1 C257.1 L2.2 R53.2 U1.H16 U1.H17 U1.J16 U1.J17 U1.K17 U1.L16 U1.L17 U1.M16 U1.M17
1V5_DDR3: C20.1 C40.1 C49.1 C66.1 C68.1 C84.2 C94.1 C96.1 C97.1 C98.1 C99.1 C100.1 C101.1 C102.1 C103.1 C104.1 C110.1 C137.1 C201.1 C202.1 C203.1 C204.1 C205.1 C206.1 C208.1 C209.1 C210.1 C211.1 C212.1 C213.1 C214.1 C215.1 C216.1 C218.1 C219.1 C220.1 C221.1 C223.1 C224.1 C225.1 C226.1 C227.1 C228.1 C229.1 C230.1 C231.1 C232.1 C233.1 C234.1 C235.1 C236.1 C237.1 C238.1 C239.1 C240.1 C258.1 C315.1 C319.1 L4.2 R10.2 R24.2 R33.1 R54.1 R78.1 R92.1 U1.J6 U1.J7 U1.K6 U1.K7 U1.L6 U1.N6 U1.P6 U1.T6 U1.T9 U1.T10 U1.U6 U1.U7 U1.V5 U1.V6 U1.V7 U1.V8 U1.V9 U1.V11 U1.V12 U1.V13 U1.V14 U1.W4 U1.W5 U1.W6 U1.W7 U1.Y4 U1.Y5 U1.Y6 U3.A1 U3.A8 U3.B2 U3.C1 U3.C9 U3.D2 U3.D9 U3.E9 U3.F1 U3.G7 U3.H2 U3.H9 U3.K2 U3.K8 U3.N1 U3.N9 U3.R1 U3.R9 U6.A1 U6.A8 U6.B2 U6.C1 U6.C9 U6.D2 U6.D9 U6.E9 U6.F1 U6.G7 U6.H2 U6.H9 U6.K2 U6.K8 U6.N1 U6.N9 U6.R1 U6.R9
3V3: C2.1 C4.1 C13.1 C25.1 C26.1 C27.1 C39.1 C46.1 C53.1 C67.1 C69.1 C91.1 C108.1 C114.1 J18.4 L5.2 Q13.2 R2.1 R3.1 R6.1 R34.1 R60.1 R88.2 R105.2 R135.1 R136.1 R140.2 R178.2 U1.V20 U1.W20 U11.4 U13.4 U15.4
3V3_MOS: C73.1 C74.1 C197.1 C198.1 C199.1 C245.1 C283.1 D2.2 D9.2 D19.2 J25.10 J25.12 LB1.2 LB4.2 LB7.2 LB8.2 LB14.1 LB17.2 LB18.1 LB20.1 LB22.1 LB35.1 Q13.3 Q15.2 R26.1 R30.1 R44.2 R47.1 R77.1 R83.2 R86.1 R94.1 R155.1 U1.D10 U1.D11 U1.D12 U1.E18 U1.F5 U1.H19 U1.J19 U1.M19 U1.N19
3V3_MOS_FLASH: C36.1 C63.1 C88.1 C93.1 C105.1 C142.1 C143.1 C275.1 C323.1 C324.1 D2.1 R12.1 R29.1 R58.1 R68.2 R80.1 R94.2 R96.2 R176.1 R177.1 R188.1 R189.1 R202.1 R203.1 R212.1 R215.1 U19.1 U19.12 U19.24 U19.34 U19.37 U22.AA3 U22.AA5 U22.K6 U22.M6 U22.N5 U22.T10 U22.U9 U22.W4 U22.Y4
3V3_SD: C263.1 C391.1 J21.4 Q15.3 R86.2 R210.1
3V3_WIFI: C21.1 C62.1 J2.5 LB4.1 U2.5 U7.8
5V0: C6.1 C58.1 C59.1 C111.1 C112.1 D4.2 J1.1 J10.1 Q14.2 R4.1 R144.1 U14.2
5V0_MOS: C56.1 C70.1 D20.2 LB2.2 LB3.2 Q14.3 R11.2 R15.2 R179.1 U10.1 U12.1
5V0_MOS_HDMI: C150.1 D20.1 J26.18 R186.2 R187.2 U4.5
AVDD11_PLL012: C12.1 C185.1 LB21.2 U1.P17
AVDD11_USB3: C16.1 C48.1 LB11.2 U1.R16 U1.R17 U1.T17
AVDD33_ADAC: C188.1 C194.1 LB35.2 U1.E19
AVDD33_PLL01: C14.1 C186.1 LB22.2 U1.R19
AVDD33_USB2: C3.1 LB17.1 U1.K19
AVDD33_USB3: C18.1 LB18.2 U1.W17 U1.W18
GND: C1.2 C2.2 C3.2 C4.2 C5.2 C7.2 C8.2 C9.2 C10.2 C11.2 C12.2 C13.2 C14.2 C15.2 C16.2 C17.2 C18.2 C19.2 C20.2 C21.2 C22.1 C23.2 C24.2 C25.2 C26.2 C27.2 C28.2 C29.2 C30.2 C31.2 C33.1 C34.2 C35.2 C36.2 C37.2 C38.2 C39.2 C40.2 C41.2 C42.1 C43.2 C44.2 C45.2 C46.2 C47.2 C48.2 C50.2 C51.2 C52.2 C53.2 C56.2 C57.2 C58.2 C59.2 C60.2 C61.2 C62.2 C63.2 C64.2 C67.2 C68.2 C69.2 C70.2 C71.2 C72.2 C74.2 C75.2 C78.2 C79.2 C85.2 C86.2 C87.2 C88.2 C89.2 C90.2 C91.2 C92.2 C93.2 C94.2 C95.2 C96.2 C97.2 C98.2 C99.2 C100.2 C101.2 C102.2 C103.2 C104.2 C105.2 C107.2 C108.2 C110.2 C111.2 C112.2 C114.2 C115.2 C116.2 C120.2 C121.2 C123.2 C124.2 C127.2 C132.2 C135.2 C137.2 C138.2 C140.2 C142.2 C143.2 C149.2 C150.2 C153.2 C154.2 C158.2 C164.2 C177.2 C182.2 C185.2 C186.2 C188.2 C189.2 C193.2 C194.2 C197.2 C198.2 C199.2 C201.2 C202.2 C203.2 C204.2 C205.2 C206.2 C209.2 C210.2 C211.2 C212.2 C213.2 C214.2 C215.2 C216.2 C218.2 C219.2 C220.2 C221.2 C224.2 C225.2 C226.2 C227.2 C228.2 C229.2 C230.2 C231.2 C232.2 C233.2 C234.2 C235.2 C236.2 C237.2 C238.2 C239.2 C240.2 C243.2 C245.2 C248.2 C250.1 C251.2 C255.1 C257.2 C258.2 C263.2 C264.2 C270.2 C271.2 C275.2 C281.2 C282.2 C283.2 C297.2 C307.2 C308.2 C313.2 C314.2 C315.2 C316.2 C317.2 C319.2 C320.2 C323.2 C324.2 C334.2 C336.2 C339.2 C363.2 C364.2 C365.2 C391.2 D1.2 D3.2 D6.2 D9.1 J1.2 J1.3 J2.2 J2.7 J2.9 J2.10 J2.12 J3.1 J4.2 J4.3 J5.2 J5.3 J10.2 J10.3 J12.4 J12.5 J12.6 J13.4 J13.7 J13.10 J13.11 J18.1 J21.6 J21.10 J21.11 J21.12 J21.13 J21.14 J21.15 J26.2 J26.5 J26.8 J26.11 J26.17 J26.20 J26.21 J26.22 J26.23 J34.5 LED1.2 Q1.2 Q2.2 Q4.2 Q5.2 R8.1 R9.2 R13.1 R18.1 R25.1 R32.1 R38.1 R39.2 R41.1 R42.1 R43.2 R45.2 R46.1 R48.2 R50.2 R51.2 R52.2 R55.2 R56.1 R57.2 R61.1 R71.1 R75.2 R82.2 R84.2 R85.2 R87.1 R89.2 R93.2 R96.1 R99.1 R100.2 R104.2 R145.2 R146.2 R149.2 R173.2 R183.2 R210.2 R229.2 S1.1 S1.3 S1.4 S2.3 S2.4 S2.5 S2.6 U1.A1 U1.A2 U1.A3 U1.A23 U1.AA2 U1.AA3 U1.AA8 U1.AA13 U1.AA14 U1.AA15 U1.AA17 U1.AA18 U1.AA20 U1.AB1 U1.AB4 U1.AB6 U1.AB10 U1.AB12 U1.AC1 U1.AC3 U1.AC5 U1.AC9 U1.AC11 U1.AC23 U1.B3 U1.B8 U1.B20 U1.B23 U1.C3 U1.C4 U1.C6 U1.C8 U1.C13 U1.C15 U1.C17 U1.C20 U1.C21 U1.C22 U1.D4 U1.D6 U1.D9 U1.D13 U1.D14 U1.D15 U1.D17 U1.D19 U1.D20 U1.D21 U1.D22 U1.E4 U1.E16 U1.E17 U1.E21 U1.E22 U1.F4 U1.F21 U1.G3 U1.G4 U1.G12 U1.G13 U1.G16 U1.G20 U1.H3 U1.H10 U1.H11 U1.H12 U1.H13 U1.H14 U1.H15 U1.H20 U1.J2 U1.J10 U1.J11 U1.J12 U1.J15 U1.J20 U1.K1 U1.K3 U1.K5 U1.K10 U1.K11 U1.K12 U1.K15 U1.K16 U1.L3 U1.L4 U1.L11 U1.L12 U1.L15 U1.L20 U1.L21 U1.M6 U1.M8 U1.M11 U1.M12 U1.M15 U1.M20 U1.N2 U1.N3 U1.N5 U1.N15 U1.N16 U1.N17 U1.P1 U1.P5 U1.P16 U1.P19 U1.P20 U1.R2 U1.R4 U1.R6 U1.R20 U1.T1 U1.T11 U1.U2 U1.U5 U1.U20 U1.V4 U1.V10 U1.V21 U1.W3 U1.W8 U1.W11 U1.W13 U1.W15 U1.W19 U1.W21 U1.Y1 U1.Y3 U1.Y7 U1.Y9 U1.Y18 U1.Y20 U1.Y23 U2.1 U2.6 U3.A9 U3.B1 U3.B3 U3.B9 U3.D1 U3.D8 U3.E1 U3.E2 U3.E8 U3.F9 U3.G1 U3.G8 U3.G9 U3.J2 U3.J8 U3.M1 U3.M9 U3.P1 U3.P9 U3.T1 U3.T9 U4.2 U5.1 U5.4 U5.10 U5.14 U6.A9 U6.B1 U6.B3 U6.B9 U6.D1 U6.D8 U6.E1 U6.E2 U6.E8 U6.F9 U6.G1 U6.G8 U6.G9 U6.J2 U6.J8 U6.M1 U6.M9 U6.P1 U6.P9 U6.T1 U6.T9 U7.1 U7.5 U10.2 U11.2 U12.2 U13.2 U14.4 U14.9 U15.2 U19.2 U19.13 U19.23 U19.25 U19.36 U19.48 U22.AA4 U22.AA6 U22.K4 U22.M7 U22.P5 U22.R10 U22.U8 U22.Y2 U22.Y5 U23.3 U23.8 U24.3 U24.8 X2.2 X2.4
VDD_AUDIO: C158.1 C320.1 R66.2 R91.1 R179.2 U5.9
ADAC_VOUTL: C350.2 R50.1 U1.B22
ADAC_VOUTR: C351.1 R183.1 U1.A22
AUDIO_L: C339.1 J34.3 R72.2
AUDIO_R: C140.1 J34.2 R74.1
CORE_CTRL: R23.2 U1.H22
CPU_CTRL: R21.2 U1.H23
CVBS: C79.1 C80.1 L6.1 R9.1 U1.E23
CVBS_OUT: C17.1 C80.2 D9.3 J34.4 L6.2
DDR_ADDR0: U1.AA12 U3.N3 U6.N3
DDR_ADDR1: U1.Y11 U3.P7 U6.P7
DDR_ADDR2: U1.W14 U3.P3 U6.P3
DDR_ADDR3: U1.AC14 U3.N2 U6.N2
DDR_ADDR4: U1.W12 U3.P8 U6.P8
DDR_ADDR5: U1.Y15 U3.P2 U6.P2
DDR_ADDR6: U1.AA10 U3.R8 U6.R8
DDR_ADDR7: U1.AB14 U3.R2 U6.R2
DDR_ADDR8: U1.AB11 U3.T8 U6.T8
DDR_ADDR9: U1.Y16 U3.R3 U6.R3
DDR_ADDR10: U1.Y8 U3.L7 U6.L7
DDR_ADDR11: U1.AB9 U3.R7 U6.R7
DDR_ADDR12: U1.Y10 U3.N7 U6.N7
DDR_ADDR13: U1.AA16 U3.T3 U6.T3
DDR_ADDR14: U1.AA11 U3.T7 U6.T7
DDR_ADDR15: U1.W10 U3.M7 U6.M7
DDR_BA0: U1.AC15 U3.M2 U6.M2
DDR_BA1: U1.AA9 U3.N8 U6.N8
DDR_BA2: U1.Y12 U3.M3 U6.M3
DDR_CASN: U1.Y14 U3.K3 U6.K3
DDR_CKE: R38.2 U1.W9 U3.K9 U6.K9
DDR_CLK1N: R16.2 R17.2 R37.1 U3.K7 U6.K7
DDR_CLK1P: R16.1 R17.1 R36.1 U3.J7 U6.J7
DDR_CSN: U1.AC12 U3.L2 U6.L2
DDR_DM0: U1.K4 U3.E7
DDR_DM1: U1.L5 U3.D3
DDR_DM2: U1.AA1 U6.E7
DDR_DM3: U1.Y2 U6.D3
DDR_DQ0: U1.H4 U3.E3
DDR_DQ1: U1.N1 U3.F7
DDR_DQ2: U1.H1 U3.F2
DDR_DQ3: U1.P3 U3.F8
DDR_DQ4: U1.H5 U3.H3
DDR_DQ5: U1.R3 U3.H8
DDR_DQ6: U1.H2 U3.G2
DDR_DQ7: U1.P2 U3.H7
DDR_DQ8: U1.M4 U3.D7
DDR_DQ9: U1.K2 U3.C3
DDR_DQ10: U1.M5 U3.C8
DDR_DQ11: U1.J3 U3.C2
DDR_DQ12: U1.N4 U3.A7
DDR_DQ13: U1.J4 U3.A2
DDR_DQ14: U1.P4 U3.B8
DDR_DQ15: U1.J5 U3.A3
DDR_DQ16: U1.T5 U6.E3
DDR_DQ17: U1.AA5 U6.F7
DDR_DQ18: U1.T2 U6.F2
DDR_DQ19: U1.AB5 U6.F8
DDR_DQ20: U1.R5 U6.H3
DDR_DQ21: U1.AC6 U6.H8
DDR_DQ22: U1.T3 U6.G2
DDR_DQ23: U1.AA6 U6.H7
DDR_DQ24: U1.AA4 U6.D7
DDR_DQ25: U1.U1 U6.C3
DDR_DQ26: U1.AB3 U6.C8
DDR_DQ27: U1.U3 U6.C2
DDR_DQ28: U1.AC2 U6.A7
DDR_DQ29: U1.T4 U6.A2
DDR_DQ30: U1.AB2 U6.B8
DDR_DQ31: U1.U4 U6.A3
DDR_DQS0N: U1.L1 U3.G3
DDR_DQS0P: U1.L2 U3.F3
DDR_DQS1N: U1.M3 U3.B7
DDR_DQS1P: U1.M2 U3.C7
DDR_DQS2N: U1.V2 U6.G3
DDR_DQS2P: U1.V3 U6.F3
DDR_DQS3N: U1.W2 U6.B7
DDR_DQS3P: U1.W1 U6.C7
DDR_ODT: U1.AB15 U3.K1 U6.K1
DDR_PLL: C11.1 C264.1 C270.1 LB7.1 U1.N8 U1.T12
DDR_RASN: U1.AB16 U3.J3 U6.J3
DDR_RESETN: C313.1 C314.1 R24.1 U1.AB13 U3.T2 U6.T2
DDR_VREF_A_CA: C49.2 C86.1 R33.2 R55.1 U3.M8
DDR_VREF_A_DQ: C208.2 C271.1 R54.2 R75.1 U3.H1
DDR_VREF_B_CA: C66.2 C87.1 R92.2 R93.1 U6.M8
DDR_VREF_B_DQ: C223.2 C308.1 R78.2 R84.1 U6.H1
DDR_WEN: U1.Y13 U3.L3 U6.L3
FE_1V1: C248.1 U1.G10
FE_3V3: C7.1 LB8.1 U1.E5
HDMI_TX0N: J26.9 U1.D16 U24.2 U24.9
HDMI_TX0P: J26.7 U1.C16 U24.1 U24.10
HDMI_TX1N: J26.6 U1.B15 U23.5 U23.6
HDMI_TX1P: J26.4 U1.A15 U23.4 U23.7
HDMI_TX2N: J26.3 U1.C14 U23.2 U23.9
HDMI_TX2P: J26.1 U1.B14 U23.1 U23.10
HDMI_TX_1V1: C78.1 C164.1 C251.1 C281.1 LB12.1 U1.G14 U1.G15
HDMI_TX_3V3: C15.1 C57.1 LB1.1 U1.E15
HDMI_TX_CEC: J26.13 R268.2 U1.C18 U4.3
HDMI_TX_HOTPLUG: C149.1 J26.19 R8.2 U1.B19 U4.4
HDMI_TX_SCL: J26.15 R186.1 U1.D18 U4.1
HDMI_TX_SDA: J26.16 R187.1 U1.A19 U4.6
HDMI_TXCN: J26.12 U1.B17 U24.5 U24.6
HDMI_TXCP: J26.10 U1.A17 U24.4 U24.7
IR_IN: D3.1 R140.1 U1.Y21
LED0_BASE: R26.2 R67.2 U1.B2
LED0_LINK_ACT: R30.2 R79.2 U1.B1
LED_GREEN: R3.2 R22.1 R48.1 U1.AB22
LED_RED: R31.1 R39.1 R60.2 U1.AC22
MUTE_CTRL: R90.1 U1.C19
NF_ALE_EMMC_PWREN: U1.N20 U19.17
NF_CLE: U1.N21 U19.16
NF_CSN0_EMMC_CMD: R212.2 U1.N22 U19.9 U22.W5
NF_DQ0_EMMC_D0: R189.2 U1.R23 U19.29 U22.H3
